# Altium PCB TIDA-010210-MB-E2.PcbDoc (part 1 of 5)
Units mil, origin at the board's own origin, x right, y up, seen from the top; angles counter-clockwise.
Board outline 11811.02 x 8661.42 mil, 4 copper layers (Top Layer, Gnd Layer, Pwr Layer, Bottom Layer), stack 94.4 mil thick; 473 components, 257 nets, 1291 pads, 289 vias.
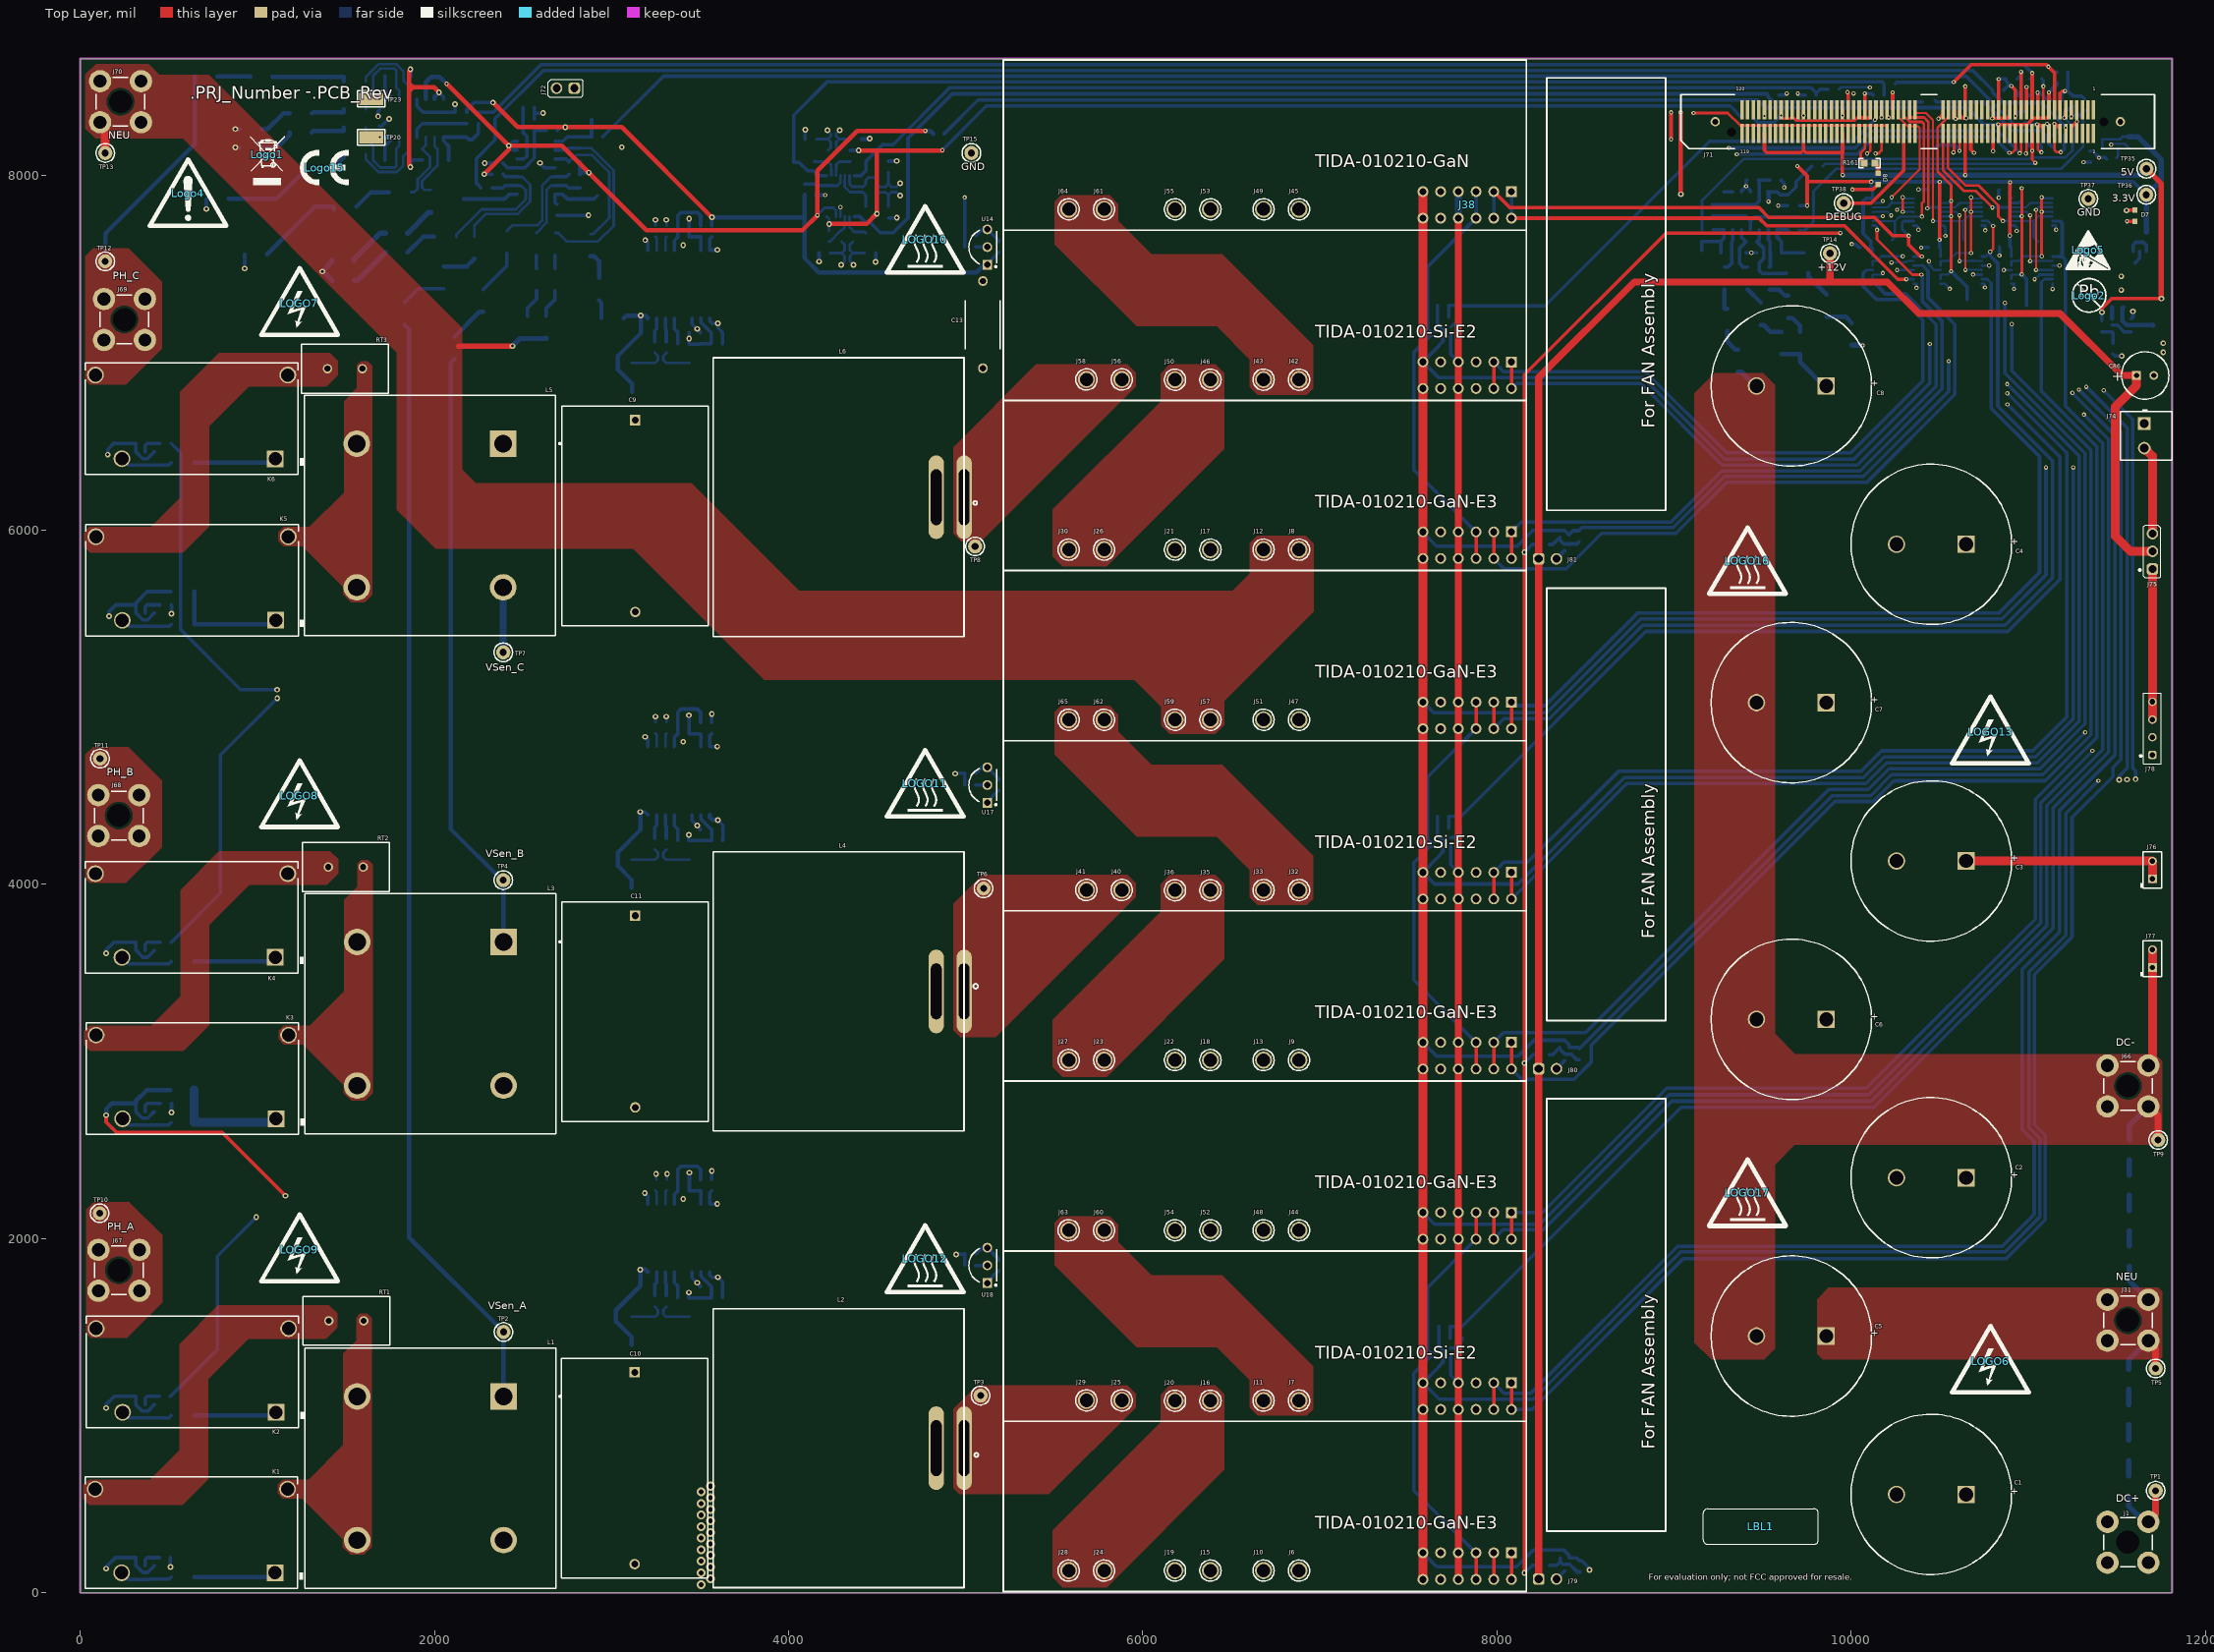
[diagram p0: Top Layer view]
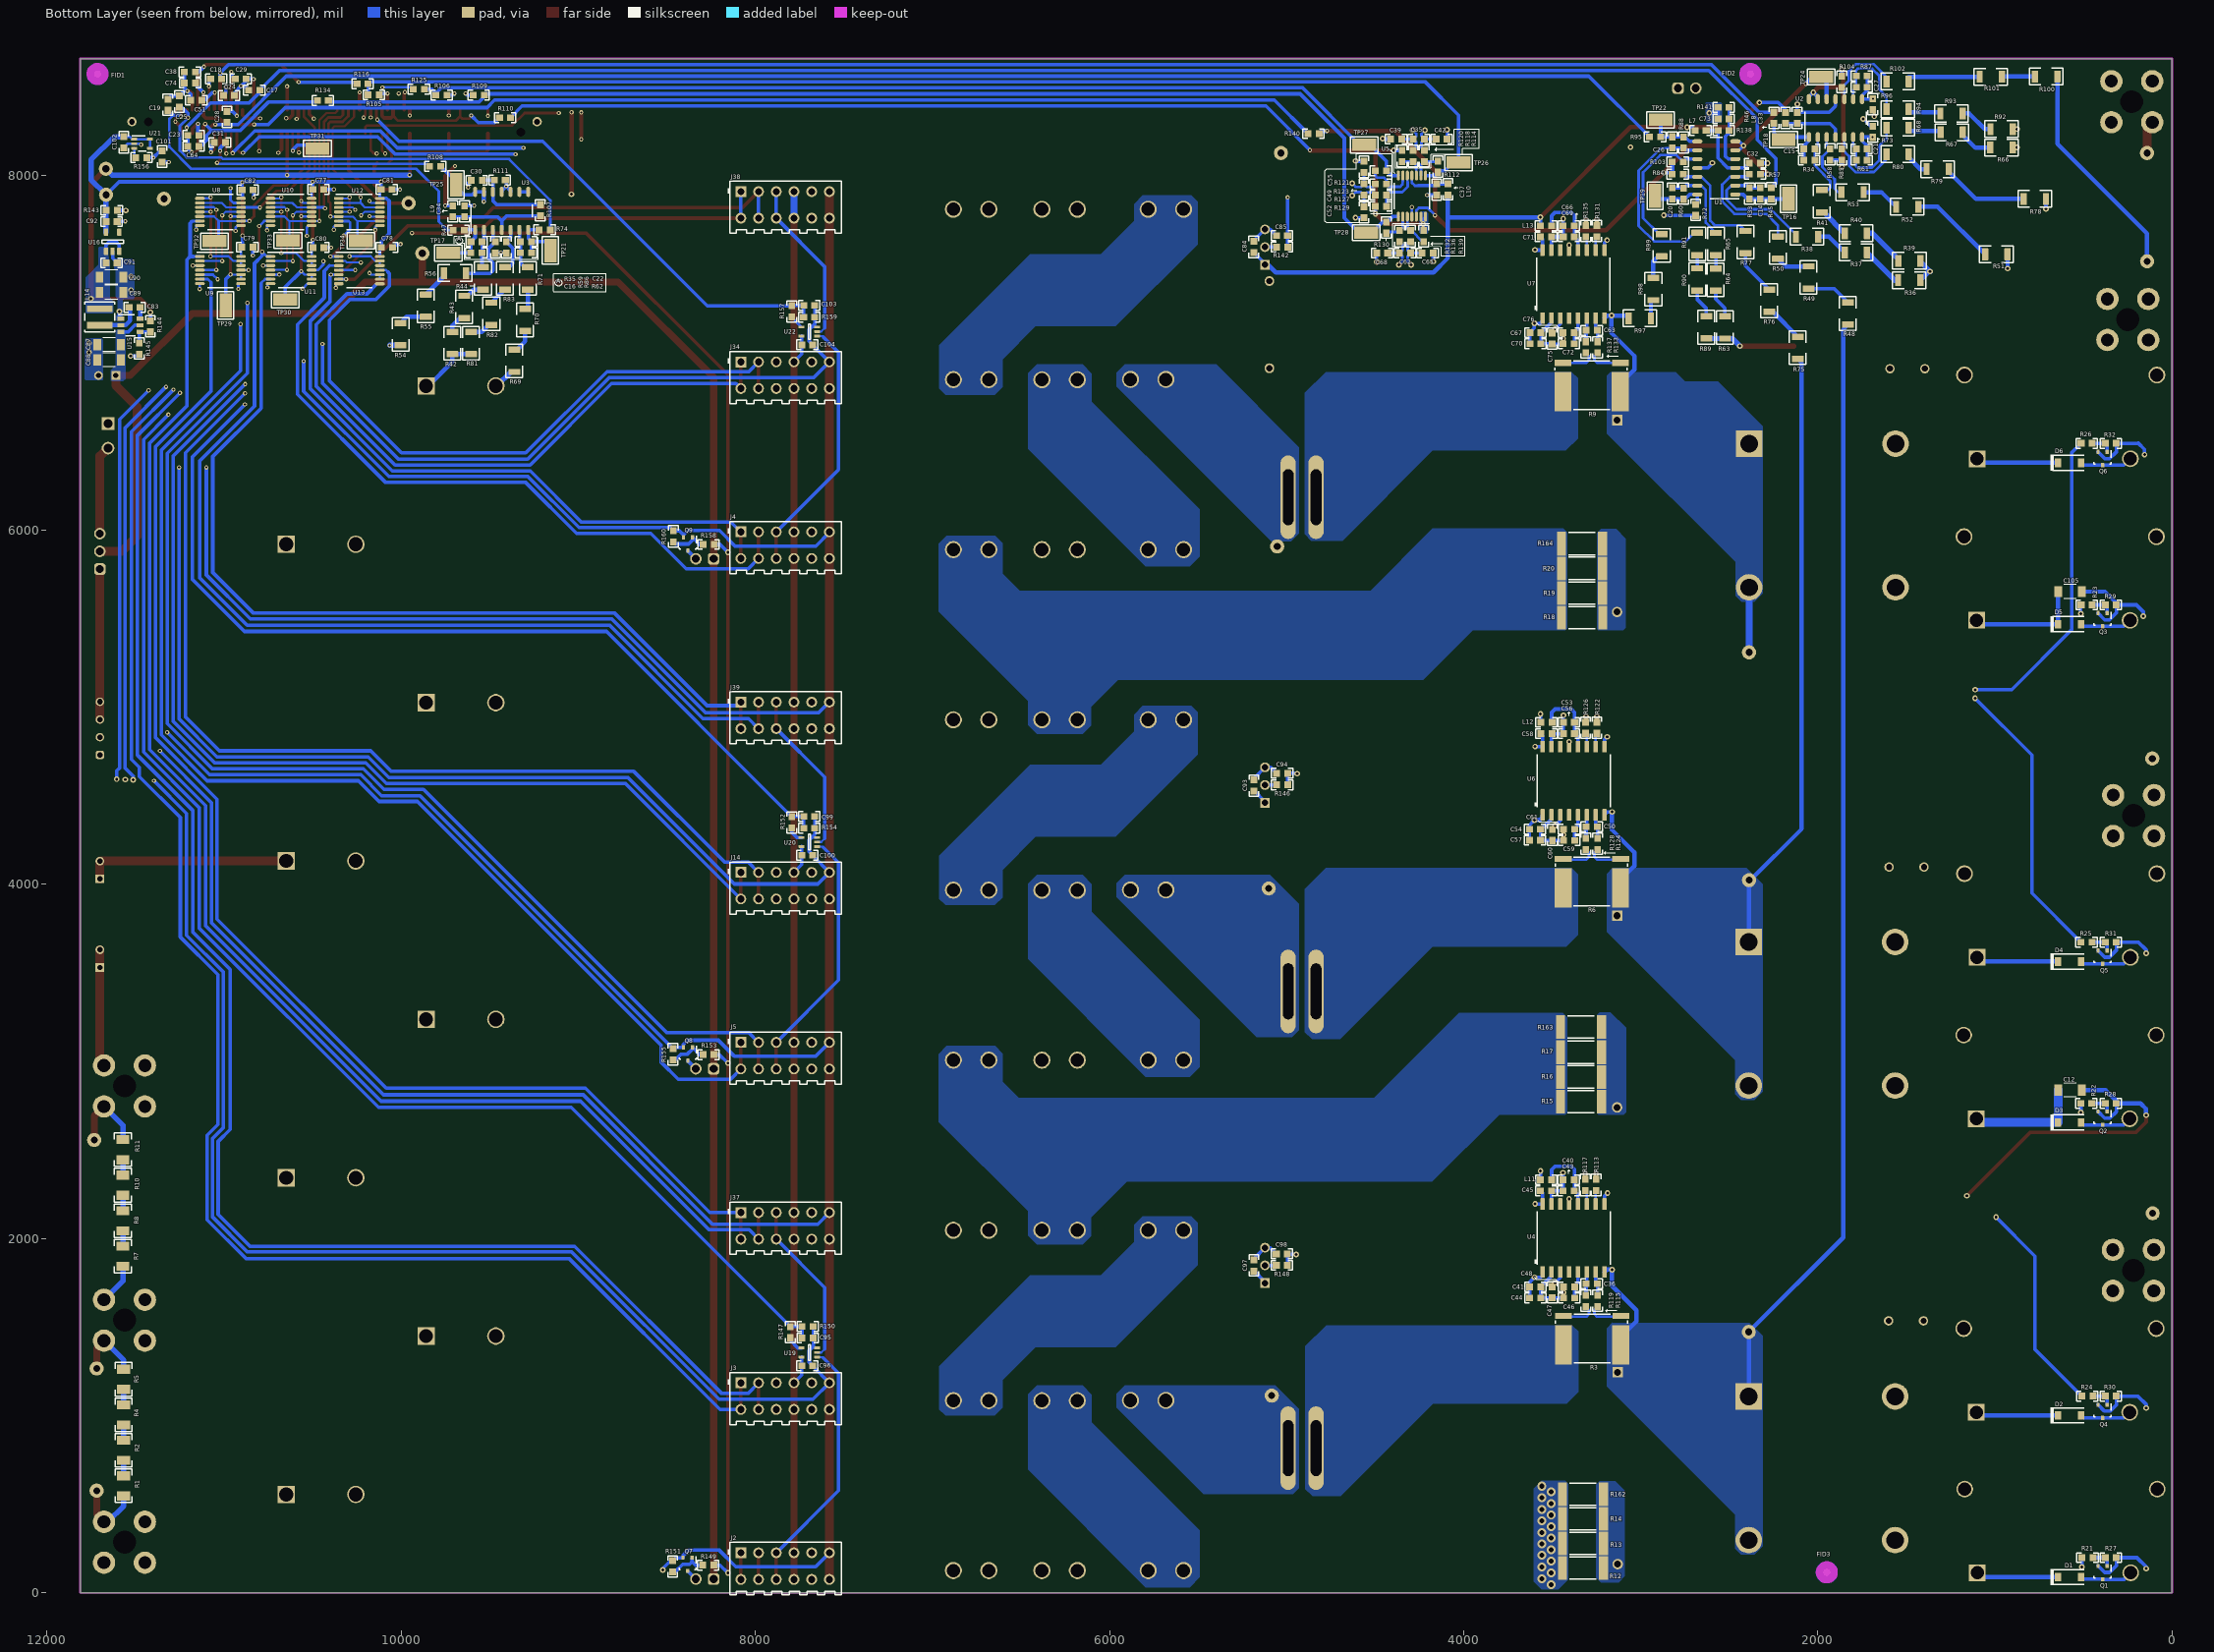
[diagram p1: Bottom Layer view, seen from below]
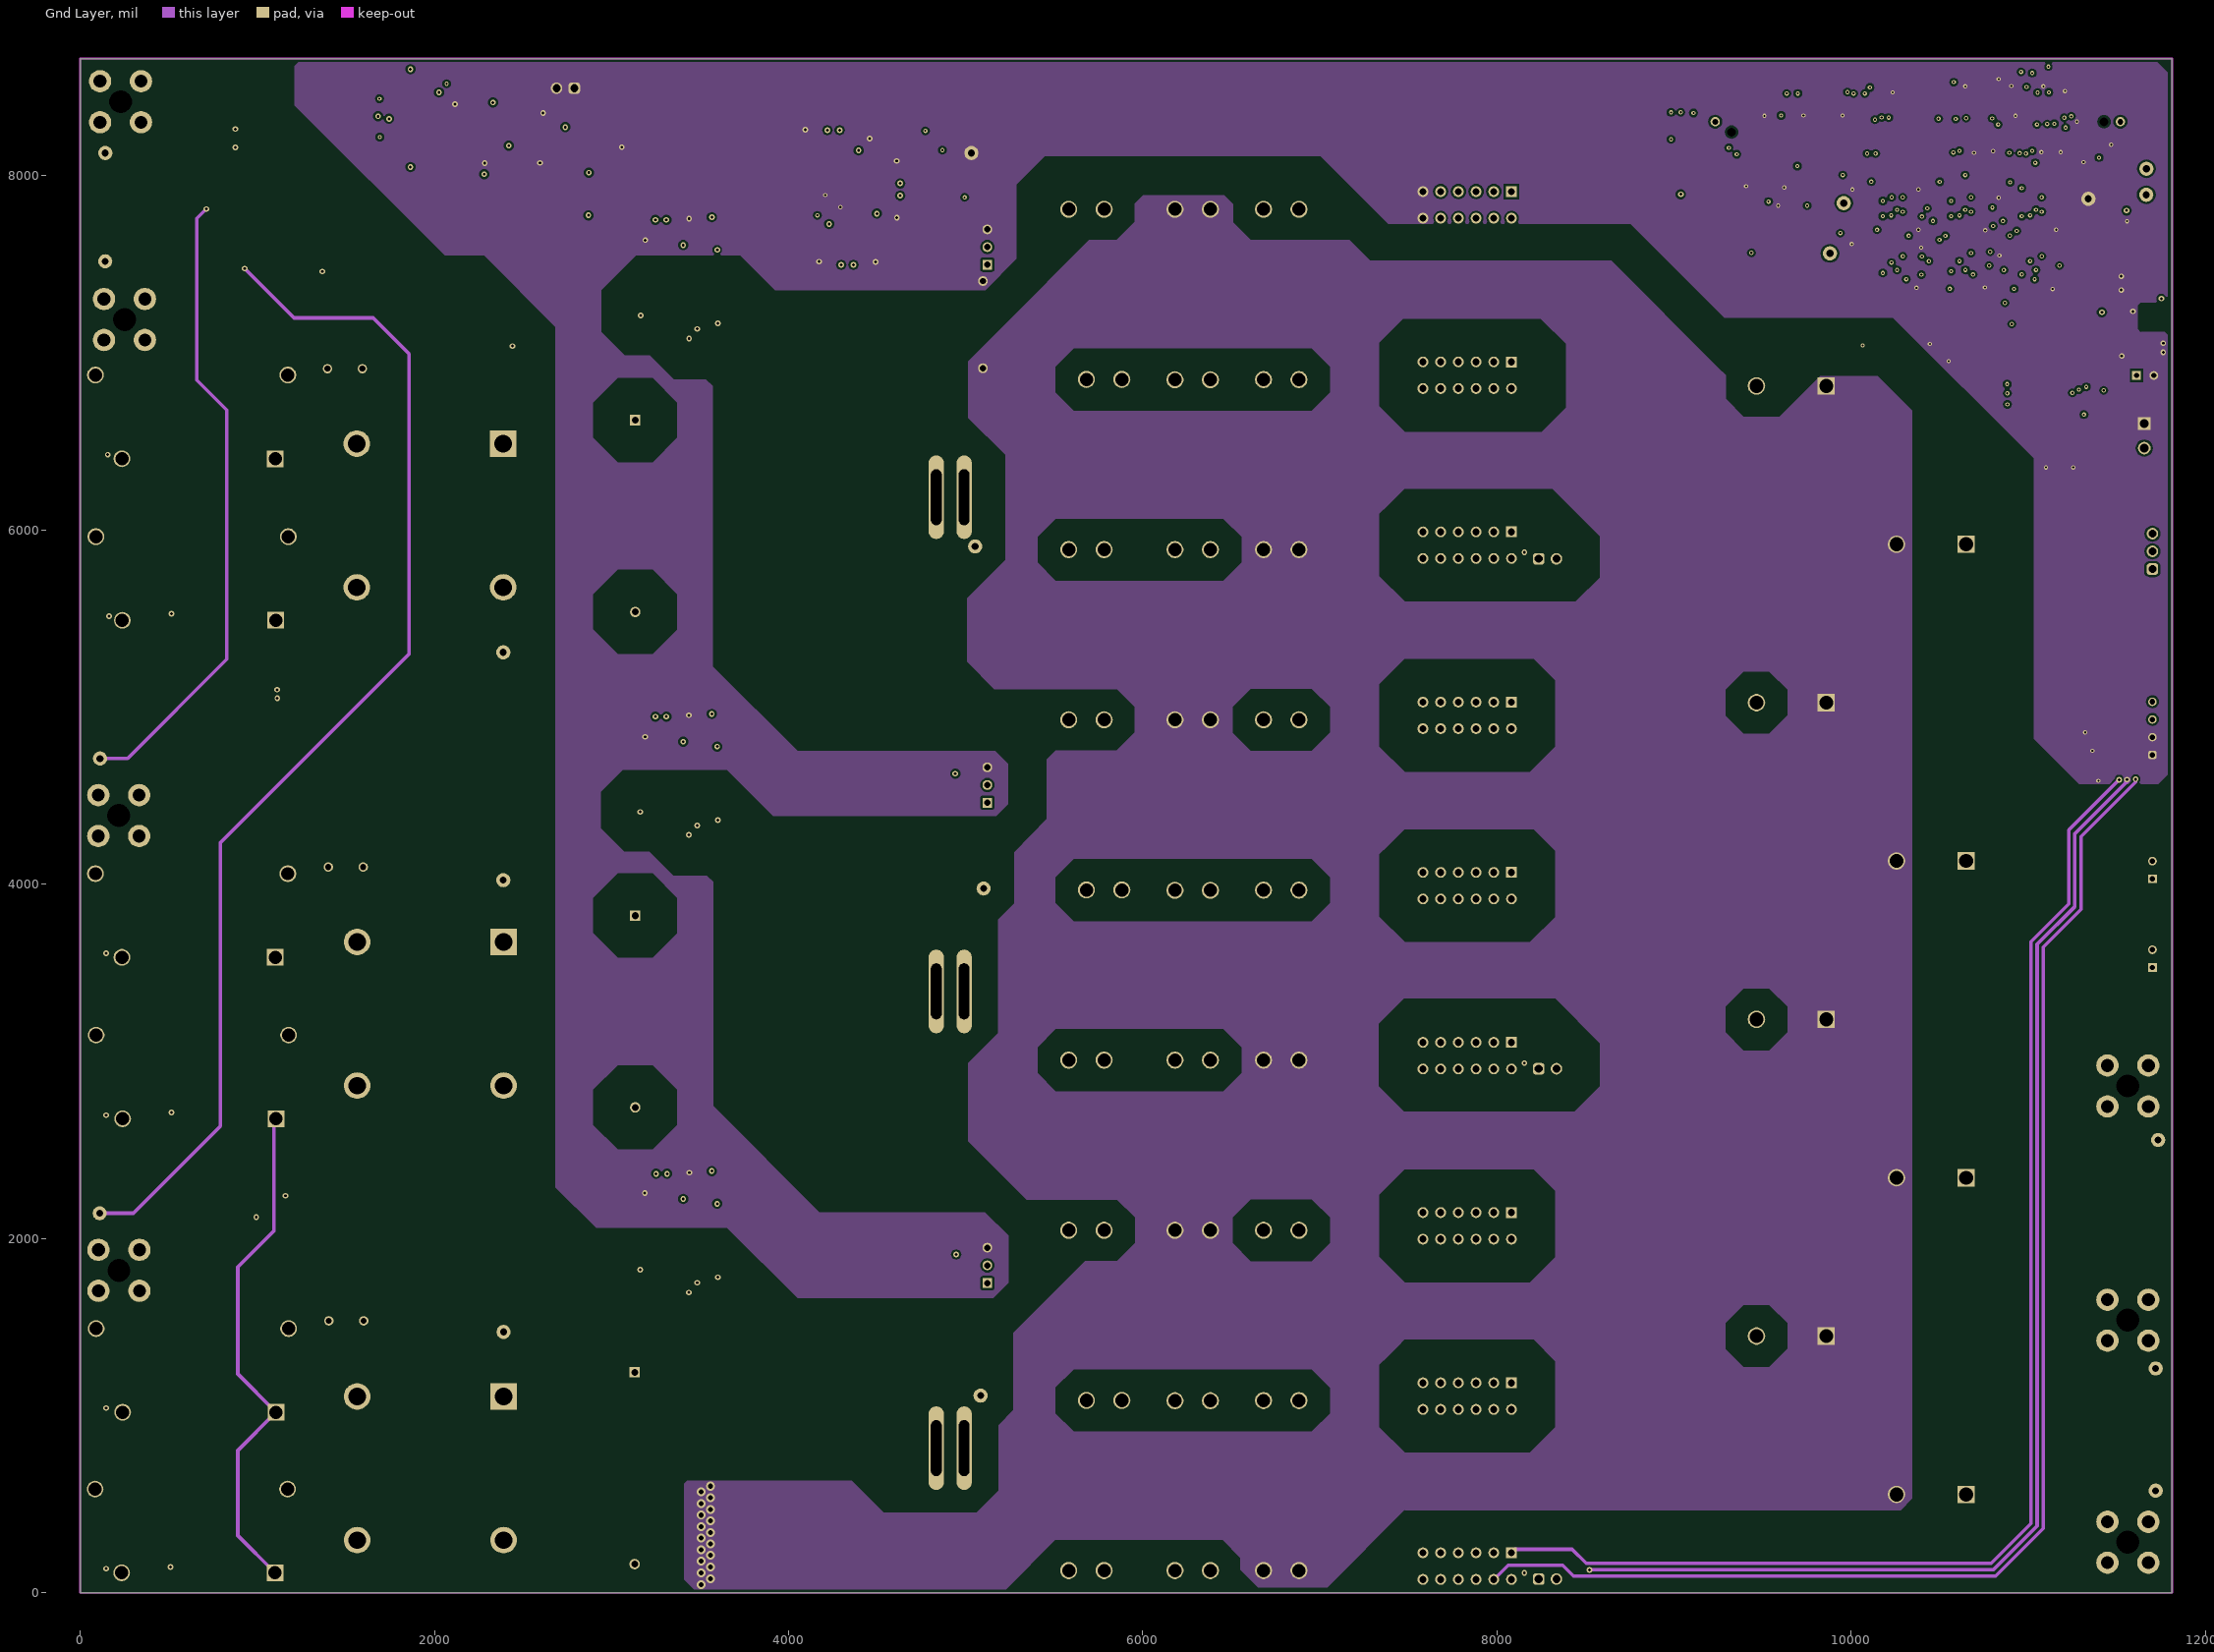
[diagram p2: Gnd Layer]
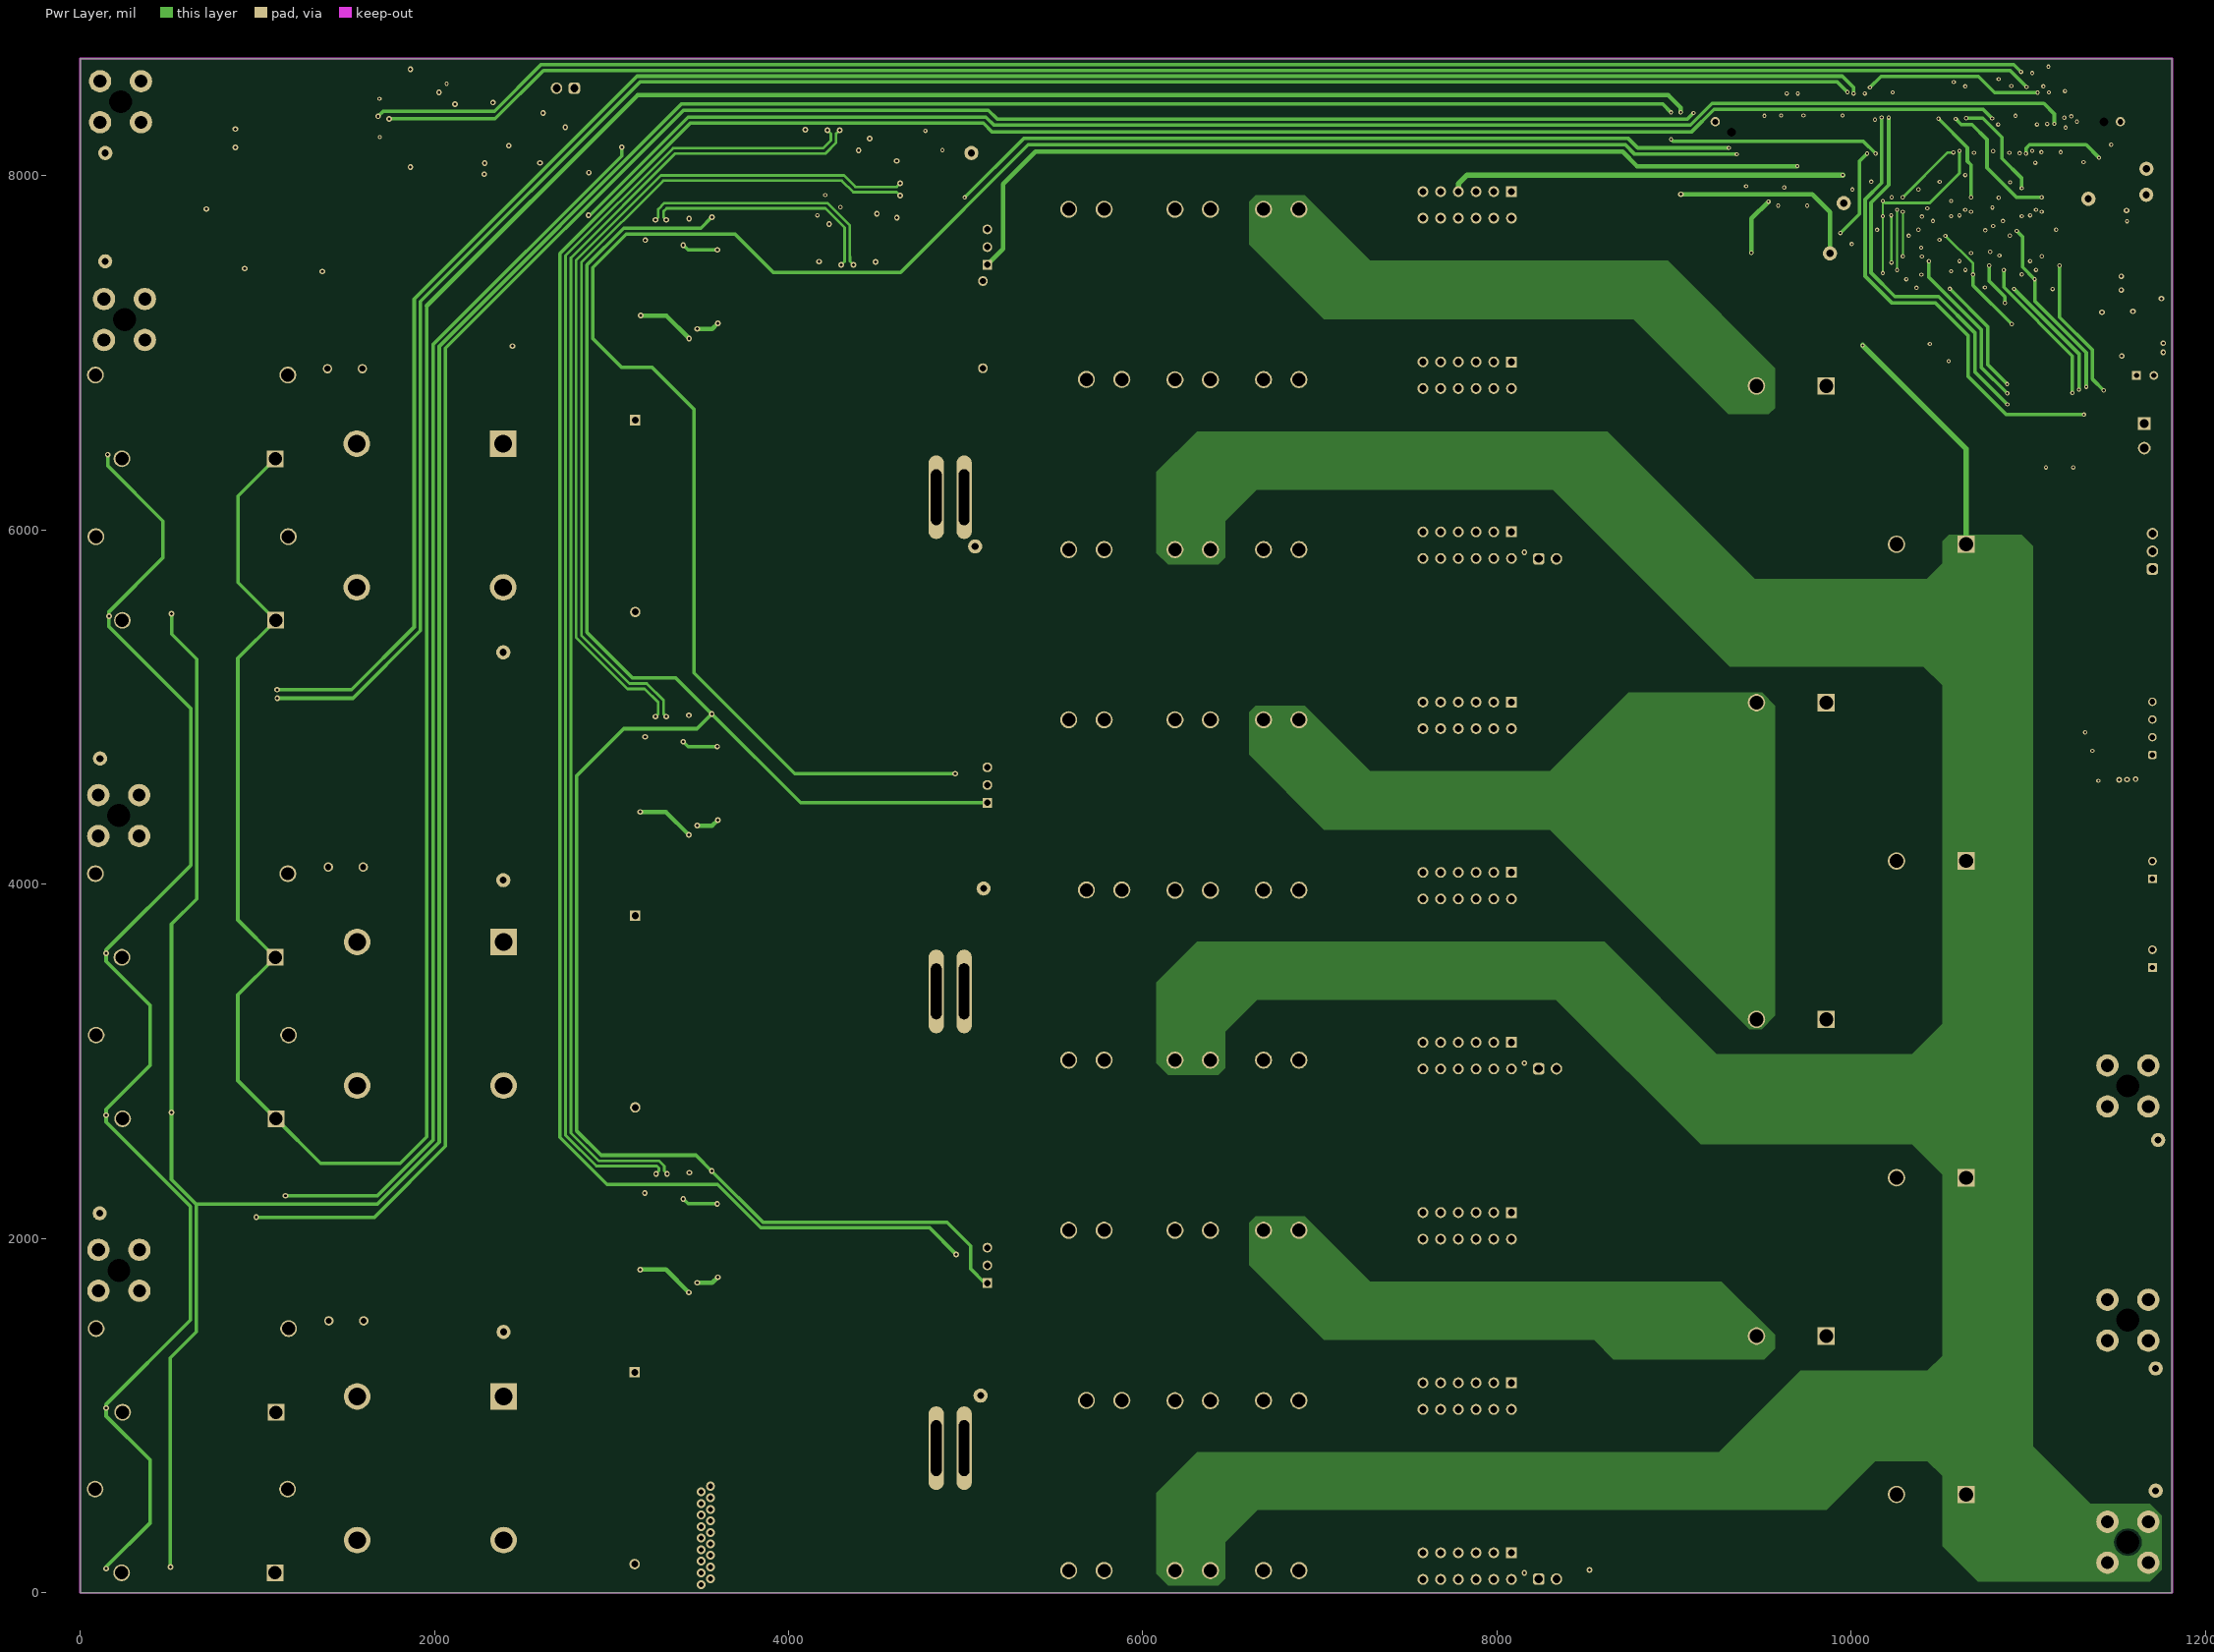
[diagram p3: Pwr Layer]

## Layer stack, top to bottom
Top Solder: solder mask 0.4, Solder Resist, Dk 3.5
Top Layer: signal copper 2.8
Dielectric 1: dielectric 12, FR-4-High Tg, Dk 4.2
Gnd Layer: signal copper 2.8
Dielectric2: core 59.2, FR-4-High Tg, Dk 4.2
Pwr Layer: signal copper 2.8
Dielectric 3: dielectric 12, FR-4-High Tg, Dk 4.2
Bottom Layer: signal copper 2.8
Bottom Solder: solder mask 0.4, Solder Resist, Dk 3.5

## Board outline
0,0 11811.02,0 11811.02,8661.42 0,8661.42

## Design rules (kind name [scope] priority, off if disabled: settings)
AcuteAngle [All] p1: minimum=4.50000000000000E+0001 checktracksonly=FALSE
AssemblyTestPointUsage [All] p1: valid=2
BoardOutlineClearance BoardOutlineClearance_MountingHoles [OnCopper and InComponentClass('Mounting Holes')] p1: gap=40 ignorepadtopadclearanceinfootprint=FALSE
BoardOutlineClearance BoardOutlineClearance_Poly [OnCopper and IsPoly] p2: gap=15 ignorepadtopadclearanceinfootprint=FALSE
BoardOutlineClearance [OnCopper and Not InComponentClass('Logo') and not InComponentClass('FiducialMark') and not InRegion(1000,500,4000,800) and not InPoly] p3: gap=0 ignorepadtopadclearanceinfootprint=FALSE
Clearance Clearance_MH [InPadClass('mh')] p1: gap=59.06 ignorepadtopadclearanceinfootprint=FALSE except(0: Arc-Hole Track-Hole SMDPad-Hole THPad-Hole Via-Hole Fill-Hole Poly-Hole Region-Hole Text-Hole)
Clearance Clearance_HV_Bottom_Layer [InLayerClass('Bottom_Layer') and InPolygon vs InNetClass('HV_Class')] p2: gap=320 ignorepadtopadclearanceinfootprint=FALSE
Clearance Clearance_HV_TOP_Layer [InLayerClass('Top_Layer') and InPolygon vs InNetClass('HV_Class')] p3: gap=320 ignorepadtopadclearanceinfootprint=FALSE
Clearance Clearance_HV_PwrLayer [InLayerClass('PWR Class') and InPolygon vs InNetClass('HV_Class')] p4: gap=200 ignorepadtopadclearanceinfootprint=FALSE
Clearance Clearance_HV_GndLayer [InLayerClass('GND_Layer') and InPolygon vs InNetClass('HV_Class')] p5: gap=200 ignorepadtopadclearanceinfootprint=FALSE
Clearance "Clearance_Poly to Poly" [InPoly vs InPoly] p6: gap=25 ignorepadtopadclearanceinfootprint=FALSE except(0: Arc-Hole Track-Hole SMDPad-Hole THPad-Hole Via-Hole Fill-Hole Poly-Hole Region-Hole Text-Hole)
Clearance Clearance_Poly [InPolygon] p7: gap=12 ignorepadtopadclearanceinfootprint=FALSE except(0: Arc-Hole Track-Hole SMDPad-Hole THPad-Hole Via-Hole Fill-Hole Poly-Hole Region-Hole Text-Hole)
Clearance [All] p8: gap=7.87 ignorepadtopadclearanceinfootprint=FALSE except(0: Arc-Arc Arc-Track Arc-SMDPad Arc-Hole Track-Hole SMDPad-Hole THPad-Hole Via-Hole Fill-Hole Poly-Hole Region-Hole Text-Hole)
ComponentClearance ComponentClearance_MountingHoles_FiducialMarks [InComponentClass('Mounting Holes') vs InComponentClass('FiducialMark')] p1: gap=30 collisioncheckmode=3 verticalgap=10 showdistances=FALSE
ComponentClearance ComponentClearance_Shunt [InComponentClass('Header') vs InComponentClass('Shunt')] p2: gap=0 collisioncheckmode=3 verticalgap=0 showdistances=FALSE
ComponentClearance ComponentClearance_Logo [InComponentClass('Logo')] p3: gap=1 collisioncheckmode=3 verticalgap=1 showdistances=FALSE
ComponentClearance ComponentClearance_ScrewToNut [(HasFootprint('NY PMS 440 0025 PH')) vs (HasFootprint('Keystone_1902C'))] p4: gap=1 collisioncheckmode=3 verticalgap=1 showdistances=FALSE
ComponentClearance ComponentClearance_MountingHoles [InComponentClass('Mounting Holes')] p5: gap=30 collisioncheckmode=3 verticalgap=100000 showdistances=FALSE
ComponentClearance ComponentClearance_SmallPassives [HasFootprint('0201*') or HasFootprint('0402*') or HasFootprint('0508') or HasFootprint('0603*') or HasFootprint('0612') or HasFootprint('0805*') or HasFootprint('0815*') or HasFootprint('0830*') or HasFootprint('1206*') or HasFootprint('1210*') or HasFootprint('1808*') or HasFootprint('1812*') or HasFootprint('1825*') or HasFootprint('2010*') or HasFootprint('2220*') or HasFootprint('2225*') or HasFootprint('2512*') or HasFootprint('2728*') or HasFootprint('3518*') vs HasFootprint('0201*') or HasFootprint('0402*') or HasFootprint('0508') or HasFootprint('0603*') or HasFootprint('0612') or HasFootprint('0805*') or HasFootprint('0815*') or HasFootprint('0830*') or HasFootprint('1206*') or HasFootprint('1210*') or HasFootprint('1808*') or HasFootprint('1812*') or HasFootprint('1825*') or HasFootprint('2010*') or HasFootprint('2220*') or HasFootprint('2225*') or HasFootprint('2512*') or HasFootprint('2728*') or HasFootprint('3518*')] p6: gap=0 collisioncheckmode=3 verticalgap=0 showdistances=FALSE
ComponentClearance ComponentClearance_THtoSMT [IsThruComponent vs IsSMTComponent] p7: gap=0 collisioncheckmode=3 verticalgap=0 showdistances=FALSE
ComponentClearance ComponentClearance_THtoTH [IsThruComponent vs IsThruComponent] p8: gap=0 collisioncheckmode=3 verticalgap=0 showdistances=FALSE
ComponentClearance [All] p9: gap=0 collisioncheckmode=3 verticalgap=0 showdistances=FALSE
DiffPairsRouting [All] p1: maxlimit=100 minlimit=10 mostfreqgap=15 toplayer_minwidth=10 toplayer_maxwidth=25 toplayer_prefwidth=15 midlayer1_minwidth=10 midlayer1_maxwidth=25 midlayer1_prefwidth=15 midlayer2_minwidth=10 midlayer2_maxwidth=25 midlayer2_prefwidth=15 bottomlayer_minwidth=10 bottomlayer_maxwidth=25 bottomlayer_prefwidth=15 maxuncoupledlength=1000
FabricationTestPointUsage TestPointUsage [All] p1: valid=2 allowmultiple=FALSE
FabricationTestpoint Testpoint [All] p1: side=3 testpointundercomponent=TRUE minsize=40 maxsize=100 preferedsize=60 minholesize=0 maxholesize=40 preferedholesize=32 testpointgrid=1 allowsidetop=TRUE allowsidebottom=TRUE usegrid=TRUE gridtolerance=0.01
FanoutControl Fanout_LCC [IsLCC] p1: bgadir=Out bgaviamode=Centered fanoutstyle=Auto fanoutdirection=Alternating viagrid=1 // Fanout_LCC (Default Rule)
FanoutControl Fanout_BGA [IsBGA] p2: bgadir=Out bgaviamode=Centered fanoutstyle=Auto fanoutdirection=Alternating viagrid=1 // Fanout_BGA (Default Rule)
FanoutControl Fanout_Default [All] p4: bgadir=Out bgaviamode=Centered fanoutstyle=Auto fanoutdirection=Alternating viagrid=1 // Fanout_Default (Default Rule)
FanoutControl Fanout_Small [(CompPinCount < 5)] p5: bgadir=Out bgaviamode=Centered fanoutstyle=Auto fanoutdirection=OutThenIn viagrid=1 // Fanout_Small (Default Rule)
Height [All] p1: minheight=0 maxheight=2500 prefheight=500
HoleSize [All] p1: absolutevalues=TRUE maxlimit=1000 minlimit=7.87 maxpercent=80.000 minpercent=20.000
MinimumAnnularRing MinimumAnnularRing_ThermalPadVias [IsVia and InAnyComponent] p1: minimumring=5.91
MinimumAnnularRing [All] p2: minimumring=5.5
MinimumSolderMaskSliver MinimumSolderMaskSliver_Logo [InComponentClass('Logo') vs InComponentClass('Logo')] p1: minsoldermaskwidth=0.7
MinimumSolderMaskSliver [All] p2: minsoldermaskwidth=3.94
PlaneConnect [All] p1: planeconnectstyle=Direct reliefexpansion=10 reliefentries=4 reliefconductorwidth=10 reliefairgap=10
PolygonConnect [All] p1: connectstyle=Direct reliefconductorwidth=10 reliefentries=4 polygonreliefangle="90 Angle" airgapwidth=10
RoutingVias ThermalPadVias [IsVia and InAnyComponent] p1: holewidth=7.87 width=19.68 viastyle="Through Hole" minholewidth=7.87 minwidth=19.68 maxholewidth=12.99 maxwidth=23.62
RoutingVias [All] p2: holewidth=16 width=32 viastyle="Through Hole" minholewidth=12 minwidth=24 maxholewidth=28 maxwidth=52
SilkToBoardRegionClearance [Not ((IsComment or IsDesignator) And (Hide <> 'False')) and not InRegion(1000,500,4000,800)] p1:
SilkToSilkClearance SilkToSilkClearance_Pb-FreeLogo [(HasFootprint('Pb-Free_Overlay_Medium') OR HasFootprint('Pb-Free_Overlay_Small')) vs (HasFootprint('Pb-Free_Overlay_Medium') OR HasFootprint('Pb-Free_Overlay_Small'))] p1: silktosilkclearance=0
SilkToSilkClearance [All] p2: silktosilkclearance=4
SilkToSolderMaskClearance SilkToComponentPadClearance [(IsPad or IsFill or IsRegion) and InAnycomponent] p1: minsilkscreentomaskgap=5 clearancetoexposedcopper=TRUE
SilkToSolderMaskClearance "Silk to Solder Mask Opening" [All] p2: minsilkscreentomaskgap=4 clearancetoexposedcopper=FALSE
SolderMaskExpansion [All] p1: expansion=1.97 istentingtop=FALSE
Width [All] p1: maxlimit=100 minlimit=9 preferedwidth=20 checkconnectedcopper=TRUE
14 further rules are at their usual default settings.

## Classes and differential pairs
component class "Power Supply and Protection-Pg3": C83 C84 C85 C86 C87 C88 C89 C90 C91 C92 C93 C94 C95 C96 C97 C98 C99 C100 C101 C102 C103 C104 D7 J72 J74 J75 J76 J77 J78 J79 J80 J81 L14 Q7 Q8 Q9 R142 R143 R144 R145 R146 R147 R148 R149 R150 R151 R152 R153 R154 R155 R156 R157 R158 R159 R160 TP35 TP36 TP37 U14 U15 U16 U17 U18 U19 U20 U21 U22
component class "Voltage Sensing-Pg4": C14 C15 C16 C17 C18 C19 C20 C21 C22 C23 C24 C25 C26 C27 C28 C29 C30 C31 C32 C33 C34 C73 C74 L7 L8 L9 R33 R34 R35 R36 R37 R38 R39 R40 R41 R42 R43 R44 R45 R46 R47 R48 R49 R50 R51 R52 R53 R54 R55 R56 R57 R58 R59 R60 R61 R62 R63 R64 R65 R66 R67 R68 R69 R70 R71 R72 R73 R74 R75 R76 R77 R78 R79 R80 R81 R82 R83 R84 R85 R86 R87 R88 R89 R90 R91 R92 R93 R94 R95 R96 R97 R98 R99 R100 R101 R102 R103 R104 R107 R108 R111 R138 R140 R141 TP16 TP17 TP18 TP19 TP20 TP21 TP22 TP23 TP24 TP25 U1 U2 U3
component class Hardware-Pg7: FID1 FID2 FID3 LBL1 Logo1 Logo2 Logo3 Logo4 Logo5 LOGO6 LOGO7 LOGO8 LOGO9 LOGO10 LOGO11 LOGO12 LOGO13 Logo15 LOGO16 LOGO17 ZZ1 ZZ2 ZZ3 ZZ4
component class FiducialMark: FID1 FID2 FID3
component class AssemblyNote: ZZ1 ZZ2 ZZ3 ZZ4
component class Label: LBL1
component class "Current Sensing-Pg5": C35 C36 C37 C38 C39 C40 C41 C42 C43 C44 C45 C46 C47 C48 C49 C50 C51 C52 C53 C54 C55 C56 C57 C58 C59 C60 C61 C62 C63 C64 C65 C66 C67 C68 C69 C70 C71 C72 C75 C76 L10 L11 L12 L13 R105 R106 R109 R110 R112 R113 R114 R115 R116 R117 R118 R119 R120 R121 R122 R123 R124 R125 R126 R127 R128 R129 R130 R131 R132 R133 R134 R135 R136 R137 R139 TP26 TP27 TP28 U4 U5 U6 U7
component class "Power Stage-Pg2": C1 C2 C3 C4 C5 C6 C7 C8 C9 C10 C11 C12 C13 C105 D1 D2 D3 D4 D5 D6 J1 J2 J3 J4 J5 J6 J7 J8 J9 J10 J11 J12 J13 J14 J15 J16 J17 J18 J19 J20 J21 J22 J23 J24 J25 J26 J27 J28 J29 J30 J31 J32 J33 J34 J35 J36 J37 J38 J39 J40 J41 J42 J43 J44 J45 J46 J47 J48 J49 J50 J51 J52 J53 J54 J55 J56 J57 J58 J59 J60 J61 J62 J63 J64 J65 J66 J67 J68 J69 J70 K1 K2 K3 K4 K5 K6 L1 L2 L3 L4 L5 L6 Q1 Q2 Q3 Q4 Q5 Q6 R1 R2 R3 R4 R5 R6 R7 R8 R9 R10 R11 R12 R13 R14 R15 R16 R17 R18 R19 R20 R21 R22 R23 R24 R25 R26 R27 R28 R29 R30 R31 R32 R162 R163 R164 RT1 RT2 RT3 TP1 TP2 TP3 TP4 TP5 TP6 TP7 TP8 TP9 TP10 TP11 TP12 TP13 TP14 TP15
component class "Controller Card-Pg6": C77 C78 C79 C80 C81 C82 D8 J71 R161 TP29 TP30 TP31 TP32 TP33 TP34 TP38 U8 U9 U10 U11 U12 U13
component class Header: J72 J75 J79 J80 J81
pad class mh: H1-1 H2-1 H3-1 H4-1 H9-1 H10-1 H11-1 H12-1 H13-1

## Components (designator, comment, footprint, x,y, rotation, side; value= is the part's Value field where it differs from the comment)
C1 "ESG157M500AQ5" ESG157M500AQ5 10451.66,555 r180 top locked value=150uF
C2 "ESG157M500AQ5" ESG157M500AQ5 10451.66,2343 r180 top locked value=150uF
C3 "ESG157M500AQ5" ESG157M500AQ5 10451.66,4131 r180 top locked value=150uF
C4 "ESG157M500AQ5" ESG157M500AQ5 10451.66,5919 r180 top locked value=150uF
C5 "ESG157M500AQ5" ESG157M500AQ5 9661.11,1449 r180 top locked value=150uF
C6 "ESG157M500AQ5" ESG157M500AQ5 9661.11,3237 r180 top locked value=150uF
C7 "ESG157M500AQ5" ESG157M500AQ5 9661.11,5025 r180 top locked value=150uF
C8 "ESG157M500AQ5" ESG157M500AQ5 9661.11,6813 r180 top locked value=150uF
C9 "B32924D3475K" B32924_31mm 3134,6078.34 r270 top locked value=4.7uF
C10 "B32924D3475K" B32924_31mm 3131,703 r270 top locked value=4.7uF
C11 "B32924D3475K" B32924_31mm 3134,3281.22 r270 top locked value=4.7uF
C12 "CGA5L1X7R1V106K160AC" 1206_190 577,2838 r180 bottom value=10uF
C13 "VY1222K47Y5UQ6TVX" VY1_1200x500_V 5097,7159 r270 top value=2200pF
C14 "06035A471JAT2A" 0603 2325.29,7899.53 r90 bottom value=470pF
C15 "06035A471JAT2A" 0603 2048.98,8150.89 r180 bottom value=470pF
C16 "06035A471JAT2A" 0603 9574.12,7564.63 r180 bottom value=470pF
C17 "C0603X103K5RACTU" 0603 10828.5,8482.84 r0 bottom value=0.01uF
C18 "C0603X103K5RACTU" 0603 11043.61,8546 r0 bottom value=0.01uF
C19 "C0603X103K5RACTU" 0603 11315.73,8400.5 r90 bottom value=0.01uF
C20 "06035A471JAT2A" 0603 2822.38,7899.53 r90 bottom value=470pF
C21 "06035A471JAT2A" 0603 1752.98,8150.96 r0 bottom value=470pF
C22 "06035A471JAT2A" 0603 9294.14,7627.47 r0 bottom value=470pF
C23 "C0603X103K5RACTU" 0603 11171.62,8228 r0 bottom value=0.01uF
C24 "C0603X103K5RACTU" 0603 10971.17,8453 r180 bottom value=0.01uF
C25 "C0603X103K5RACTU" 0603 11250.84,8419 r90 bottom value=0.01uF
C26 "06035A471JAT2A" 0603 2822.38,8187.53 r270 bottom value=470pF
C27 "06035A471JAT2A" 0603 1752.98,8498.98 r0 bottom value=470pF
C28 "C0603X103K5RACTU" 0603 10982,8331.39 r90 bottom value=0.01uF
C29 "C0603X103K5RACTU" 0603 10905,8546 r180 bottom value=0.01uF
C30 "C0603X104K3RACTU" 0603 9572,7974 r180 bottom value=0.1uF
C31 "C0603X103K5RACTU" 0603 11022.5,8187 r0 bottom value=0.01uF
C32 "C0603X104K3RACTU" 0603 2355.83,8070.53 r0 bottom value=0.1uF
C33 "C0603X104K3RACTU" 0603 2116.98,8325.97 r270 bottom value=0.1uF
C34 "C0603X104K3RACTU" 0603 9641,7799 r270 bottom value=0.1uF
C35 "GRM1885C1H332JA01D" 0603 4253.47,8206.91 r0 bottom value=3300pF
C36 "C0603X103K5RACTU" 0603 3277,1744 r0 bottom value=0.01uF
C37 "C0603X104K3RACTU" 0603 4153,7922 r90 bottom value=0.1uF
C38 "GRM1885C1H221JA01D" 0603 11191.55,8585 r0 bottom value=220pF
C39 "06035A331JAT2A" 0603 4381.47,8206.91 r0 bottom value=330pF
C40 "GRJ188R71E105KE11D" 0603 3407.94,2331.78 r0 bottom value=1uF
C41 "C0603X104K3RACTU" 0603 3595.94,1726.46 r0 bottom value=0.1uF
C42 "06035A331JAT2A" 0603 4125.02,8206.91 r180 bottom value=330pF
C43 "GRM188R71H102JA01D" 0603 3407.94,2268.78 r0 bottom value=1000pF
C44 "GRJ188R71E105KE11D" 0603 3595.94,1663.46 r180 bottom value=1uF
C45 "C0603X104K3RACTU" 0603 3534.94,2268.78 r0 bottom value=0.1uF
C46 "C0603X104K3RACTU" 0603 3404.94,1663.46 r180 bottom value=0.1uF
C47 "GRM188R71H102JA01D" 0603 3500,1696.5 r270 bottom value=1000pF
C48 "GRM188R71H102JA01D" 0603 3404.94,1726.46 r0 bottom value=1000pF
C49 "GRM1885C1H332JA01D" 0603 4563.47,7921.76 r270 bottom value=3300pF
C50 "C0603X103K5RACTU" 0603 3277.43,4324 r0 bottom value=0.01uF
C51 "GRM1885C1H221JA01D" 0603 11155.48,8426 r0 bottom value=220pF
C52 "06035A331JAT2A" 0603 4563.47,7793.76 r270 bottom value=330pF
C53 "GRJ188R71E105KE11D" 0603 3405.86,4913.74 r0 bottom value=1uF
C54 "C0603X104K3RACTU" 0603 3597.55,4311 r0 bottom value=0.1uF
C55 "06035A331JAT2A" 0603 4563.47,8050.22 r90 bottom value=330pF
C56 "GRM188R71H102JA01D" 0603 3405.86,4849.74 r0 bottom value=1000pF
C57 "GRJ188R71E105KE11D" 0603 3597.55,4248 r180 bottom value=1uF
C58 "C0603X104K3RACTU" 0603 3532.86,4849.74 r0 bottom value=0.1uF
C59 "C0603X104K3RACTU" 0603 3404.93,4247 r180 bottom value=0.1uF
C60 "GRM188R71H102JA01D" 0603 3499,4278 r270 bottom value=1000pF
C61 "GRM188R71H102JA01D" 0603 3404.93,4310 r0 bottom value=1000pF
C62 "GRM1885C1H332JA01D" 0603 4331.53,7562.91 r180 bottom value=3300pF
C63 "C0603X103K5RACTU" 0603 3277.54,7127 r0 bottom value=0.01uF
C64 "GRM1885C1H221JA01D" 0603 11171.87,8165.16 r0 bottom value=220pF
C65 "06035A331JAT2A" 0603 4203.53,7562.91 r180 bottom value=330pF
C66 "GRJ188R71E105KE11D" 0603 3407,7716.78 r0 bottom value=1uF
C67 "C0603X104K3RACTU" 0603 3595,7114 r0 bottom value=0.1uF
C68 "06035A331JAT2A" 0603 4459.98,7562.91 r0 bottom value=330pF
C69 "GRM188R71H102JA01D" 0603 3406.93,7654.61 r0 bottom value=1000pF
C70 "GRJ188R71E105KE11D" 0603 3595,7051 r180 bottom value=1uF
C71 "C0603X104K3RACTU" 0603 3535,7654.61 r0 bottom value=0.1uF
C72 "C0603X104K3RACTU" 0603 3407,7051 r180 bottom value=0.1uF
C73 "C0603X104K3RACTU" 0603 2533,8320.39 r180 bottom value=0.1uF
C74 "C0603X103K5RACTU" 0603 11191.17,8523 r0 bottom value=0.01uF
C75 "GRM188R71H102JA01D" 0603 3500.93,7081 r270 bottom value=1000pF
C76 "GRM188R71H102JA01D" 0603 3407,7114 r0 bottom value=1000pF
C77 "C0603X104K3RACTU" 0603 10466.82,7922.18 r0 bottom value=0.1uF
C78 "C0603X104K3RACTU" 0603 10079.19,7594.78 r0 bottom value=0.1uF
C79 "C0603X104K3RACTU" 0603 10867.35,7596.18 r0 bottom value=0.1uF
C80 "C0603X104K3RACTU" 0603 10465.82,7594.18 r0 bottom value=0.1uF
C81 "C0603X104K3RACTU" 0603 10081.19,7921.78 r0 bottom value=0.1uF
C82 "C0603X104K3RACTU" 0603 10866,7920 r0 bottom value=0.1uF
C83 "C0603X104K3RACTU" 0603 11504,7256.91 r180 bottom value=0.1uF
C84 "C0603X104K3RACTU" 0603 5185.05,7598.06 r270 bottom value=0.1uF
C85 "C0603X104K3RACTU" 0603 5026.05,7661.11 r180 bottom value=0.1uF
C86 "EEU-EB1E101S" CAPPR250W50D630H1120 11659,6871.91 r0 top value=100uF
C87 "CGA5L1X7R1V106K160AC" 1206_190 11648,7044.93 r0 bottom value=10uF
C88 "CGA5L1X7R1V106K160AC" 1206_190 11648,6958.93 r0 bottom value=10uF
C89 "GRM31CR71A226KE15L" 1206_180 11635,7340.91 r180 bottom value=22uF
C90 "GRM31CR71A226KE15L" 1206_180 11635,7426.91 r180 bottom value=22uF
C91 "CC0603KRX7R7BB225" 0603 11634.01,7507.71 r180 bottom value=2.2uF
C92 "CC0603KRX7R7BB225" 0603 11634.01,7740.71 r180 bottom value=2.2uF
C93 "C0603X104K3RACTU" 0603 5185,4557 r270 bottom value=0.1uF
C94 "C0603X104K3RACTU" 0603 5025,4626 r180 bottom value=0.1uF
C95 "06035A331JAT2A" 0603 7704,1438.26 r180 bottom value=330pF
C96 "C0603X104K3RACTU" 0603 7706.09,1281.34 r0 bottom value=0.1uF
C97 "C0603X104K3RACTU" 0603 5185,1847.81 r270 bottom value=0.1uF
C98 "C0603X104K3RACTU" 0603 5027,1913 r180 bottom value=0.1uF
C99 "06035A331JAT2A" 0603 7695,4382 r180 bottom value=330pF
C100 "C0603X104K3RACTU" 0603 7706,4163.13 r0 bottom value=0.1uF
C101 "C0603X104K3RACTU" 0603 11348.68,8108 r90 bottom value=0.1uF
C102 "C0603X104K3RACTU" 0603 11564.73,8188.75 r90 bottom value=0.1uF
C103 "06035A331JAT2A" 0603 7695,7267 r180 bottom value=330pF
C104 "C0603X104K3RACTU" 0603 7706,7045.02 r0 bottom value=0.1uF
C105 "CGA5L1X7R1V106K160AC" 1206_190 577,5652 r180 bottom value=10uF
D1 "1N4148WQ-7-F" SOD-123 579,88 r180 bottom value=100V
D2 "1N4148WQ-7-F" SOD-123 579,1001 r180 bottom value=100V
D3 "1N4148WQ-7-F" SOD-123 579,2655 r180 bottom value=100V
D4 "1N4148WQ-7-F" SOD-123 579,3563 r180 bottom value=100V
D5 "1N4148WQ-7-F" SOD-123 579,5468 r180 bottom value=100V
D6 "1N4148WQ-7-F" SOD-123 579,6379 r180 bottom value=100V
D7 "150060VS55040" WL-SMCD-0603 11601,7773.91 r90 top value=Green
D8 "150060VS55040" WL-SMCD-0603 10150.54,7982 r90 top value=Green
FID1 "Fiducial" Fiducial10-30 11713,8574 r180 bottom
FID2 "Fiducial" Fiducial10-30 2381,8574 r180 bottom
FID3 "Fiducial" Fiducial10-30 1950,115 r180 bottom
J1 "74650073R" Wurth_WP-THRBU 11561.45,285 r0 top locked
J2 "0448120024" Molex_0448120024#1 7831.32,150.11 r180 bottom
J3 "0448120024" Molex_0448120024#1 7831.32,1109.74 r180 bottom
J4 "0448120024" Molex_0448120024#1 7831.32,5913.89 r180 bottom
J5 "0448120024" Molex_0448120024#1 7831.32,3032 r180 bottom
J6 "Suggest using a net name here" Mill-Max_0312-0-15-15-34-27-10-0 6881.32,125.11 r0 top
J7 "Suggest using a net name here" Mill-Max_0312-0-15-15-34-27-10-0 6881.32,1084.74 r0 top
J8 "Suggest using a net name here" Mill-Max_0312-0-15-15-34-27-10-0 6881.32,5888.89 r0 top
J9 "Suggest using a net name here" Mill-Max_0312-0-15-15-34-27-10-0 6881.32,3007 r0 top
J10 "Suggest using a net name here" Mill-Max_0312-0-15-15-34-27-10-0 6681.32,125.11 r0 top
J11 "Suggest using a net name here" Mill-Max_0312-0-15-15-34-27-10-0 6681.32,1084.74 r0 top
J12 "Suggest using a net name here" Mill-Max_0312-0-15-15-34-27-10-0 6681.32,5888.89 r0 top
J13 "Suggest using a net name here" Mill-Max_0312-0-15-15-34-27-10-0 6681.32,3007 r0 top
J14 "0448120024" Molex_0448120024#1 7831.32,3991.63 r180 bottom
J15 "Suggest using a net name here" Mill-Max_0312-0-15-15-34-27-10-0 6381.32,125.11 r0 top
J16 "Suggest using a net name here" Mill-Max_0312-0-15-15-34-27-10-0 6381.32,1083.95 r0 top
J17 "Suggest using a net name here" Mill-Max_0312-0-15-15-34-27-10-0 6381.32,5888.89 r0 top
J18 "Suggest using a net name here" Mill-Max_0312-0-15-15-34-27-10-0 6381.32,3007 r0 top
J19 "Suggest using a net name here" Mill-Max_0312-0-15-15-34-27-10-0 6181.32,125.11 r0 top
J20 "Suggest using a net name here" Mill-Max_0312-0-15-15-34-27-10-0 6181.32,1083.95 r0 top
J21 "Suggest using a net name here" Mill-Max_0312-0-15-15-34-27-10-0 6181.32,5888.89 r0 top
J22 "Suggest using a net name here" Mill-Max_0312-0-15-15-34-27-10-0 6181.32,3007 r0 top
J23 "Suggest using a net name here" Mill-Max_0312-0-15-15-34-27-10-0 5781.32,3007 r0 top
J24 "Suggest using a net name here" Mill-Max_0312-0-15-15-34-27-10-0 5781.32,125.11 r0 top
J25 "Suggest using a net name here" Mill-Max_0312-0-15-15-34-27-10-0 5881.32,1085.74 r0 top
J26 "Suggest using a net name here" Mill-Max_0312-0-15-15-34-27-10-0 5781.32,5888.89 r0 top
J27 "Suggest using a net name here" Mill-Max_0312-0-15-15-34-27-10-0 5581.32,3007 r0 top
J28 "Suggest using a net name here" Mill-Max_0312-0-15-15-34-27-10-0 5581.32,125.11 r0 top
J29 "Suggest using a net name here" Mill-Max_0312-0-15-15-34-27-10-0 5681.32,1085.74 r0 top
J30 "Suggest using a net name here" Mill-Max_0312-0-15-15-34-27-10-0 5581.32,5888.89 r0 top
J31 "74650073R" Wurth_WP-THRBU 11561.45,1538.5 r0 top locked
J32 "Suggest using a net name here" Mill-Max_0312-0-15-15-34-27-10-0 6881.32,3966.63 r0 top
J33 "Suggest using a net name here" Mill-Max_0312-0-15-15-34-27-10-0 6681.32,3966.63 r0 top
J34 "0448120024" Molex_0448120024#1 7831.32,6873.52 r180 bottom
J35 "Suggest using a net name here" Mill-Max_0312-0-15-15-34-27-10-0 6381.32,3965.84 r0 top
J36 "Suggest using a net name here" Mill-Max_0312-0-15-15-34-27-10-0 6181.32,3965.84 r0 top
J37 "0448120024" Molex_0448120024#1 7831.32,2071.37 r180 bottom
J38 "0448120024" Molex_0448120024#2 7831.32,7835.15 r180 top
J39 "0448120024" Molex_0448120024#1 7831.32,4953.26 r180 bottom
J40 "Suggest using a net name here" Mill-Max_0312-0-15-15-34-27-10-0 5881.32,3967.63 r0 top
J41 "Suggest using a net name here" Mill-Max_0312-0-15-15-34-27-10-0 5681.32,3967.63 r0 top
J42 "Suggest using a net name here" Mill-Max_0312-0-15-15-34-27-10-0 6881.32,6848.52 r0 top
J43 "Suggest using a net name here" Mill-Max_0312-0-15-15-34-27-10-0 6681.32,6848.52 r0 top
J44 "Suggest using a net name here" Mill-Max_0312-0-15-15-34-27-10-0 6881.32,2046.37 r0 top
J45 "Suggest using a net name here" Mill-Max_0312-0-15-15-34-27-10-0 6881.32,7810.15 r0 top
J46 "Suggest using a net name here" Mill-Max_0312-0-15-15-34-27-10-0 6381.32,6847.73 r0 top
J47 "Suggest using a net name here" Mill-Max_0312-0-15-15-34-27-10-0 6881.32,4928.26 r0 top
J48 "Suggest using a net name here" Mill-Max_0312-0-15-15-34-27-10-0 6681.32,2046.37 r0 top
J49 "Suggest using a net name here" Mill-Max_0312-0-15-15-34-27-10-0 6681.32,7810.15 r0 top
J50 "Suggest using a net name here" Mill-Max_0312-0-15-15-34-27-10-0 6181.32,6847.73 r0 top
J51 "Suggest using a net name here" Mill-Max_0312-0-15-15-34-27-10-0 6681.32,4928.26 r0 top
J52 "Suggest using a net name here" Mill-Max_0312-0-15-15-34-27-10-0 6381.32,2046.37 r0 top
J53 "Suggest using a net name here" Mill-Max_0312-0-15-15-34-27-10-0 6381.32,7810.15 r0 top
J54 "Suggest using a net name here" Mill-Max_0312-0-15-15-34-27-10-0 6181.32,2046.37 r0 top
J55 "Suggest using a net name here" Mill-Max_0312-0-15-15-34-27-10-0 6181.32,7810.15 r0 top
J56 "Suggest using a net name here" Mill-Max_0312-0-15-15-34-27-10-0 5881.32,6849.52 r0 top
J57 "Suggest using a net name here" Mill-Max_0312-0-15-15-34-27-10-0 6381.32,4928.26 r0 top
J58 "Suggest using a net name here" Mill-Max_0312-0-15-15-34-27-10-0 5681.32,6849.52 r0 top
J59 "Suggest using a net name here" Mill-Max_0312-0-15-15-34-27-10-0 6181.32,4928.26 r0 top
J60 "Suggest using a net name here" Mill-Max_0312-0-15-15-34-27-10-0 5781.32,2046.37 r0 top
J61 "Suggest using a net name here" Mill-Max_0312-0-15-15-34-27-10-0 5781.32,7810.15 r0 top
J62 "Suggest using a net name here" Mill-Max_0312-0-15-15-34-27-10-0 5781.32,4928.26 r0 top
J63 "Suggest using a net name here" Mill-Max_0312-0-15-15-34-27-10-0 5581.32,2046.37 r0 top
J64 "Suggest using a net name here" Mill-Max_0312-0-15-15-34-27-10-0 5581.32,7810.15 r0 top
J65 "Suggest using a net name here" Mill-Max_0312-0-15-15-34-27-10-0 5581.32,4928.26 r0 top
J66 "74650073R" Wurth_WP-THRBU 11561.45,2861 r0 top locked
J67 "74650073R" Wurth_WP-THRBU 219.06,1820.38 r0 top
J68 "74650073R" Wurth_WP-THRBU 218.06,4387.57 r0 top
J69 "74650073R" Wurth_WP-THRBU 250.06,7188.22 r0 top
J70 "74650073R" Wurth_WP-THRBU 227.95,8417.55 r0 top
J71 "HSEC8-160-01-L-DV-A-BL" controlCARD-120HSEC 10447.81,8305.87 r180 top locked
J72 "61300211121" WURTH_61300211121 2740,8493.92 r180 top
J74 "691214110002" Wurth_691214110002 11654,6531.1 r270 top
J75 "61300311121" WURTH_61300311121 11700,5879 r90 top
J76 "310-13-102-41-001000" Mill-max_310-13-102-41-001000 11700,4080 r90 top
J77 "310-13-102-41-001000" Mill-max_310-13-102-41-001000 11700,3580 r90 top
J78 "310-13-104-41-001000" Mill-max_310-13-104-41-001000 11700,4880 r90 top
J79 "61300211121" WURTH_61300211121 8285,77 r0 top
J80 "61300211121" WURTH_61300211121 8285,2958 r0 top
J81 "61300211121" WURTH_61300211121 8285,5837 r0 top
K1 "G4A-1A-PE DC12" RELAY_G4A-1A-PE 628,339 r180 top locked
K2 "G4A-1A-PE DC12" RELAY_G4A-1A-PE 633.56,1245.38 r180 top locked
K3 "G4A-1A-PE DC12" RELAY_G4A-1A-PE 633.69,2901.94 r180 top locked
K4 "G4A-1A-PE DC12" RELAY_G4A-1A-PE 629.56,3813.38 r180 top locked
K5 "G4A-1A-PE DC12" RELAY_G4A-1A-PE 632,5716 r180 top locked
K6 "G4A-1A-PE DC12" RELAY_G4A-1A-PE 629.56,6628.38 r180 top locked
L1 "7443783533220" FP-7443783533220_PTH_34MM5_36MM-MFG 1977.39,702.51 r0 top locked
L2 "750344413" 750344413 4282.34,816 r180 top locked value=480uH
L3 "7443783533220" FP-7443783533220_PTH_34MM5_36MM-MFG 1977.39,3268.51 r0 top locked
L4 "750344413" 750344413 4282.34,3395 r180 top locked value=480uH
L5 "7443783533220" FP-7443783533220_PTH_34MM5_36MM-MFG 1975.39,6081.51 r0 top locked
L6 "750344413" 750344413 4282.34,6185 r180 top locked value=480uH
L7 "74279228260" 0603 2662.46,8255.85 r180 bottom value="26 ohm"
L8 "74279228260" 0603 2182.98,8325.97 r270 bottom value="26 ohm"
L9 "74279228260" 0603 9707,7799 r270 bottom value="26 ohm"
L10 "74279228260" 0603 4089,7923 r90 bottom value="26 ohm"
L11 "74279228260" 0603 3534.94,2331.78 r0 bottom value="26 ohm"
L12 "74279228260" 0603 3532.93,4913.74 r0 bottom value="26 ohm"
L13 "74279228260" 0603 3535,7716.78 r0 bottom value="26 ohm"
L14 "XAL4030-332MEB" XAL4030 11701,7201.91 r90 bottom value=3.3uH
LBL1 "THT-14-423-10" Label_650x200 9489,373.55 r0 top
Logo1 "WEEE logo" WEEE_Minimum 1055.11,8119 r0 top
Logo2 "Pb-Free Symbol" Pb-Free_Overlay_Medium 11341.92,7324 r0 top
Logo3 "FCC disclaimer" FCC_disclaimer 10705,-2146.45 r0 top
Logo4 "CAUTION.  READ USER GUIDE BEFORE USE" IEC_Caution_Medium 609.43,7899 r0 top
Logo5 "ESD Susceptible" ESD_Overlay_Medium 11337,7580 r0 top
LOGO6 "DANGER HIGH VOLTAGE" IEC_HighVoltage_Medium 10785.45,1306 r0 top
LOGO7 "DANGER HIGH VOLTAGE" IEC_HighVoltage_Medium 1239,7278 r0 top
LOGO8 "DANGER HIGH VOLTAGE" IEC_HighVoltage_Medium 1239,4498.5 r0 top
LOGO9 "DANGER HIGH VOLTAGE" IEC_HighVoltage_Medium 1239,1935 r0 top
LOGO10 "CAUTION HOT SURFACE" IEC_HotSurface_Medium 4771,7640.14 r0 top
LOGO11 "CAUTION HOT SURFACE" IEC_HotSurface_Medium 4771,4569 r0 top
LOGO12 "CAUTION HOT SURFACE" IEC_HotSurface_Medium 4771,1885 r0 top
LOGO13 "DANGER HIGH VOLTAGE" IEC_HighVoltage_Medium 10785.45,4859 r0 top
Logo15 "CE Mark" CE_Mark_5mm 1379.11,8045.51 r0 top
LOGO16 "CAUTION HOT SURFACE" IEC_HotSurface_Medium 9414,5826 r0 top
LOGO17 "CAUTION HOT SURFACE" IEC_HotSurface_Medium 9414,2258 r0 top
Q1 "BSS138PW,115" SOT-323 393,114 r270 bottom value=60V
Q2 "BSS138PW,115" SOT-323 393,2679 r270 bottom value=60V
Q3 "BSS138PW,115" SOT-323 393,5493 r270 bottom value=60V
Q4 "BSS138PW,115" SOT-323 393,1024 r270 bottom value=60V
Q5 "BSS138PW,115" SOT-323 393,3588 r270 bottom value=60V
Q6 "BSS138PW,115" SOT-323 393,6403 r270 bottom value=60V
Q7 "BSS138PW,115" SOT-323 8382,160 r270 bottom value=60V
Q8 "BSS138PW,115" SOT-323 8380,3041.5 r270 bottom value=60V
Q9 "BSS138PW,115" SOT-323 8380,5921 r270 bottom value=60V
R1 "RC1206FR-07100KL" 1206 11566,603.23 r270 bottom value=100k
R2 "RC1206FR-07100KL" 1206 11566,803.8 r270 bottom value=100k
R3 "WSL40262L000FEB" WSL4026_310 3275,1435 r180 bottom value=0.002
R4 "RC1206FR-07100KL" 1206 11566,1004.37 r270 bottom value=100k
R5 "RC1206FR-07100KL" 1206 11566,1204.94 r270 bottom value=100k
R6 "WSL40262L000FEB" WSL4026_310 3276.93,4015 r180 bottom value=0.002
R7 "RC1206FR-07100KL" 1206 11570,1899.52 r270 bottom value=100k
R8 "RC1206FR-07100KL" 1206 11570,2100.09 r270 bottom value=100k
R9 "WSL40262L000FEB" WSL4026_310 3278,6816 r180 bottom value=0.002
R10 "RC1206FR-07100KL" 1206 11570,2300.66 r270 bottom value=100k
R11 "RC1206FR-07100KL" 1206 11570,2501.23 r270 bottom value=100k
R12 "35222R2JT" 2512 3327,139 r180 bottom value=2.2
R13 "35222R2JT" 2512 3327,278 r180 bottom value=2.2
R14 "35222R2JT" 2512 3327,417 r180 bottom value=2.2
R15 "35222R2JT" 2512 3338,2773 r180 bottom value=2.2
R16 "35222R2JT" 2512 3338,2912 r180 bottom value=2.2
R17 "35222R2JT" 2512 3338.02,3051 r180 bottom value=2.2
R18 "35222R2JT" 2512 3331.66,5505 r180 bottom value=2.2
R19 "35222R2JT" 2512 3332,5644 r180 bottom value=2.2
R20 "35222R2JT" 2512 3332,5783 r180 bottom value=2.2
R21 "ESR03EZPJ101" 0603 478,198 r180 bottom value=100
R22 "ESR03EZPJ101" 0603 485,2763 r180 bottom value=100
R23 "ESR03EZPJ101" 0603 483,5577 r180 bottom value=100
R24 "ESR03EZPJ101" 0603 479,1110 r180 bottom value=100
R25 "ESR03EZPJ101" 0603 484,3673 r180 bottom value=100
R26 "ESR03EZPJ101" 0603 483,6489 r180 bottom value=100
R27 "ERJ-3EKF1002V" 0603 347,198 r0 bottom value=10.0k
R28 "ERJ-3EKF1002V" 0603 347,2763 r0 bottom value=10.0k
R29 "ERJ-3EKF1002V" 0603 347,5577 r0 bottom value=10.0k
R30 "ERJ-3EKF1002V" 0603 347,1110 r0 bottom value=10.0k
R31 "ERJ-3EKF1002V" 0603 347,3673 r0 bottom value=10.0k
R32 "ERJ-3EKF1002V" 0603 347,6489 r0 bottom value=10.0k
R33 "RG1608P-123-B-T5" 0603 2387.29,7899.53 r270 bottom value=12.0k
R34 "RG1608P-123-B-T5" 0603 2048.98,8087.4 r0 bottom value=12.0k
R35 "RT0603BRD0710K5L" 0603 9573.59,7627.47 r0 bottom value=10.5k
R36 "TNPV12061M00BEEN" TNPV1206 1484.47,7410 r0 bottom value=1.00Meg
R37 "TNPV12061M00BEEN" TNPV1206 1786,7567 r0 bottom value=1.00Meg
R38 "TNPV12061M00BEEN" TNPV1206 2062,7655 r0 bottom value=1.00Meg
R39 "TNPV12061M00BEEN" TNPV1206 1484,7519 r0 bottom value=1.00Meg
R40 "TNPV12061M00BEEN" TNPV1206 1786,7675 r0 bottom value=1.00Meg
R41 "TNPV12061M00BEEN" TNPV1206 1978,7856 r90 bottom value=1.00Meg
R42 "TNPV12061M00BEEN" TNPV1206 9710,7055 r90 bottom value=1.00Meg
R43 "TNPV12061M00BEEN" TNPV1206 9643,7259 r90 bottom value=1.00Meg
R44 "TNPV12061M00BEEN" TNPV1206 9537,7420 r90 bottom value=1.00Meg
R45 "CRCW060368R1FKEA" 0603 2263,7900 r90 bottom value=68.1
R46 "CRCW060368R1FKEA" 0603 2249,8326.5 r90 bottom value=68.1
R47 "CRCW060368R1FKEA" 0603 9675,7692 r0 bottom value=68.1
R48 "TNPV12061M00BEEN" TNPV1206 1831,7222 r90 bottom value=1.00Meg
R49 "TNPV12061M00BEEN" TNPV1206 2053,7425 r90 bottom value=1.00Meg
R50 "TNPV12061M00BEEN" TNPV1206 2226,7594 r90 bottom value=1.00Meg
R51 "TNPV12061M00BEEN" TNPV1206 993,7556.15 r0 bottom value=1.00Meg
R52 "TNPV12061M00BEEN" TNPV1206 1496,7824 r0 bottom value=1.00Meg
R53 "TNPV12061M00BEEN" TNPV1206 1805,7907 r0 bottom value=1.00Meg
R54 "TNPV12061M00BEEN" TNPV1206 10002.86,7105 r90 bottom value=1.00Meg
R55 "TNPV12061M00BEEN" TNPV1206 9860,7266.01 r90 bottom value=1.00Meg
R56 "TNPV12061M00BEEN" TNPV1206 9695,7449.53 r180 bottom value=1.00Meg
R57 "RG1608P-123-B-T5" 0603 2355.83,8008.53 r0 bottom value=12.0k
R58 "RG1608P-123-B-T5" 0603 1931.53,8119.94 r90 bottom value=12.0k
R59 "RT0603BRD0710K5L" 0603 9467,7595.63 r90 bottom value=10.5k
R60 "RG1608P-123-B-T5" 0603 2758.92,7898.53 r270 bottom value=12.0k
R61 "RG1608P-123-B-T5" 0603 1752.98,8087.4 r180 bottom value=12.0k
R62 "RT0603BRD0710K5L" 0603 9294.17,7564.63 r180 bottom value=10.5k
R63 "TNPV12061M00BEEN" TNPV1206 2525.07,7143.23 r90 bottom value=1.00Meg
R64 "TNPV12061M00BEEN" TNPV1206 2577,7413 r90 bottom value=1.00Meg
R65 "TNPV12061M00BEEN" TNPV1206 2575.76,7614 r90 bottom value=1.00Meg
R66 "TNPV12061M00BEEN" TNPV1206 964,8158.73 r0 bottom value=1.00Meg
R67 "TNPV12061M00BEEN" TNPV1206 1245,8245 r0 bottom value=1.00Meg
R68 "TNPV12061M00BEEN" TNPV1206 1550,8271 r0 bottom value=1.00Meg
R69 "TNPV12061M00BEEN" TNPV1206 9360,6955 r90 bottom value=1.00Meg
R70 "TNPV12061M00BEEN" TNPV1206 9299,7186 r90 bottom value=1.00Meg
R71 "TNPV12061M00BEEN" TNPV1206 9284,7420 r90 bottom value=1.00Meg
R72 "CRCW060368R1FKEA" 0603 2691,7807 r270 bottom value=68.1
R73 "CRCW060368R1FKEA" 0603 1690,8247.64 r90 bottom value=68.1
R74 "CRCW060368R1FKEA" 0603 9188.79,7693.99 r180 bottom value=68.1
R75 "TNPV12061M00BEEN" TNPV1206 2114,7027.99 r90 bottom value=1.00Meg
R76 "TNPV12061M00BEEN" TNPV1206 2275,7294 r90 bottom value=1.00Meg
R77 "TNPV12061M00BEEN" TNPV1206 2409,7625 r90 bottom value=1.00Meg
R78 "TNPV12061M00BEEN" TNPV1206 775.6,7869 r0 bottom value=1.00Meg
R79 "TNPV12061M00BEEN" TNPV1206 1324,8037 r0 bottom value=1.00Meg
R80 "TNPV12061M00BEEN" TNPV1206 1550,8121 r0 bottom value=1.00Meg
R81 "TNPV12061M00BEEN" TNPV1206 9604.37,7055 r90 bottom value=1.00Meg
R82 "TNPV12061M00BEEN" TNPV1206 9489.76,7220.01 r90 bottom value=1.00Meg
R83 "TNPV12061M00BEEN" TNPV1206 9412.62,7420 r90 bottom value=1.00Meg
R84 "RG1608P-123-B-T5" 0603 2791.83,8008.46 r180 bottom value=12.0k
R85 "RG1608P-123-B-T5" 0603 1865,8119.94 r90 bottom value=12.0k
R86 "RT0603BRD0710K5L" 0603 9405.17,7595.63 r90 bottom value=10.5k
R87 "RG1608P-123-B-T5" 0603 1752.98,8562.54 r180 bottom value=12.0k
R88 "RG1608P-123-B-T5" 0603 2758.38,8187.17 r90 bottom value=12.0k
R89 "TNPV12061M00BEEN" TNPV1206 2630.07,7144.23 r90 bottom value=1.00Meg
R90 "TNPV12061M00BEEN" TNPV1206 2682,7414 r90 bottom value=1.00Meg
R91 "TNPV12061M00BEEN" TNPV1206 2682,7614.24 r90 bottom value=1.00Meg
R92 "TNPV12061M00BEEN" TNPV1206 963.24,8262.84 r0 bottom value=1.00Meg
R93 "TNPV12061M00BEEN" TNPV1206 1246,8351 r0 bottom value=1.00Meg
R94 "TNPV12061M00BEEN" TNPV1206 1550,8375 r0 bottom value=1.00Meg
R95 "CRCW060368R1FKEA" 0603 2919.2,8219.02 r0 bottom value=68.1
R96 "CRCW060368R1FKEA" 0603 1690,8403 r270 bottom value=68.1
R97 "TNPV12061M00BEEN" TNPV1206 3006,7195 r180 bottom value=1.00Meg
R98 "TNPV12061M00BEEN" TNPV1206 2929.24,7359.94 r90 bottom value=1.00Meg
R99 "TNPV12061M00BEEN" TNPV1206 2882,7607 r90 bottom value=1.00Meg
R100 "TNPV12061M00BEEN" TNPV1206 711.54,8559.39 r0 bottom value=1.00Meg
R101 "TNPV12061M00BEEN" TNPV1206 1024,8558 r0 bottom value=1.00Meg
R102 "TNPV12061M00BEEN" TNPV1206 1550,8532 r0 bottom value=1.00Meg
R103 "RG1608P-123-B-T5" 0603 2791.72,8078.05 r180 bottom value=12.0k
R104 "RG1608P-123-B-T5" 0603 1865,8530 r270 bottom value=12.0k
R105 "RCS06030000Z0EA" 0603 10153.72,8456 r180 bottom value=0
R106 "RCS06030000Z0EA" 0603 9771,8455.57 r180 bottom value=0
R107 "RG1608P-103-B-T5" 0603 9213,7805 r90 bottom value=10.0k
R108 "CRCW060368R1FKEA" 0603 9807,8053 r0 bottom value=68.1
R109 "RCS06030000Z0EA" 0603 9561,8455.57 r0 bottom value=0
R110 "RCS06030000Z0EA" 0603 9412.5,8328 r0 bottom value=0
R111 "RG1608P-103-B-T5" 0603 9442.14,7975.27 r180 bottom value=10.0k
R112 "PHT0603Y1002BGT200" 0603 4145.47,8050.91 r270 bottom value=10.0k
R113 "RC0603FR-0749R9L" 0603 3251.89,2301.78 r90 bottom value=49.9
R114 "RT0603BRD0715KL" 0603 4222.47,8110.91 r270 bottom value=15.0k
R115 "CRCW060310R0FKEA" 0603 3244,1648 r90 bottom value=10.0
R116 "CRCW0603499RFKEAC" 0603 10217,8519.47 r0 bottom value=499
R117 "RC0603FR-0749R9L" 0603 3313.87,2301.78 r90 bottom value=49.9
R118 "RT0603BRD0715KL" 0603 4285.47,8110.91 r270 bottom value=15.0k
R119 "CRCW060310R0FKEA" 0603 3309.91,1648 r90 bottom value=10.0
R120 "PHT0603Y1002BGT200" 0603 4348.47,8110.91 r270 bottom value=10.0k
R121 "PHT0603Y1002BGT200" 0603 4467.47,8027.63 r180 bottom value=10.0k
R122 "RC0603FR-0749R9L" 0603 3247.86,4883 r90 bottom value=49.9
R123 "RT0603BRD0715KL" 0603 4467.47,7952.76 r180 bottom value=15.0k
R124 "CRCW060310R0FKEA" 0603 3244.44,4228 r90 bottom value=10.0
R125 "CRCW0603499RFKEAC" 0603 9899,8488.49 r0 bottom value=499
R126 "RC0603FR-0749R9L" 0603 3311.86,4882.74 r90 bottom value=49.9
R127 "RT0603BRD0715KL" 0603 4467.47,7889.91 r180 bottom value=15.0k
R128 "CRCW060310R0FKEA" 0603 3309.93,4228 r90 bottom value=10.0
R129 "PHT0603Y1002BGT200" 0603 4467.47,7826.91 r180 bottom value=10.0k
R130 "PHT0603Y1002BGT200" 0603 4436.47,7706.91 r90 bottom value=10.0k
R131 "RC0603FR-0749R9L" 0603 3247.93,7687 r90 bottom value=49.9
R132 "RT0603BRD0715KL" 0603 4362.53,7658.91 r90 bottom value=15.0k
R133 "CRCW060310R0FKEA" 0603 3244.54,7031 r90 bottom value=10.0
R134 "CRCW0603499RFKEAC" 0603 10441,8425 r0 bottom value=499
R135 "RC0603FR-0749R9L" 0603 3311,7687 r90 bottom value=49.9
R136 "RT0603BRD0715KL" 0603 4299.53,7658.91 r90 bottom value=15.0k
R137 "CRCW060310R0FKEA" 0603 3310.54,7031 r90 bottom value=10.0
R138 "RG1608P-103-B-T5" 0603 2533.02,8255.85 r180 bottom value=10.0k
R139 "PHT0603Y1002BGT200" 0603 4226,7659.14 r270 bottom value=10.0k
R140 "CRCW060368R1FKEA" 0603 4848,8237 r0 bottom value=68.1
R141 "RG1608P-103-B-T5" 0603 2533,8385 r0 bottom value=10.0k
R142 "RC0603FR-072K26L" 0603 5025.55,7597.06 r180 bottom value=2.26k
R143 "RC0603FR-07820RL" 0603 11633,7804.19 r180 bottom value=820
R144 "RC0603FR-0756K2L" 0603 11414.52,7149.6 r90 bottom value=56.2k
R145 "ERJ-3EKF1002V" 0603 11478,7024 r90 bottom value=10.0k
R146 "RC0603FR-072K26L" 0603 5025,4561 r180 bottom value=2.26k
R147 "RC0603FR-071K69L" 0603 7802,1471 r90 bottom value=1.69k
R148 "RC0603FR-072K26L" 0603 5027,1849 r180 bottom value=2.26k
R149 "ESR03EZPJ101" 0603 8265.5,155.73 r0 bottom value=100
R150 "RC0603FR-073K3L" 0603 7704,1503.26 r0 bottom value=3.30k
R151 "ERJ-3EKF1002V" 0603 8466,149 r270 bottom value=10.0k
R152 "RC0603FR-071K69L" 0603 7793,4349 r90 bottom value=1.69k
R153 "ESR03EZPJ101" 0603 8263.5,3038 r0 bottom value=100
R154 "RC0603FR-073K3L" 0603 7695,4316 r0 bottom value=3.30k
R155 "ERJ-3EKF1002V" 0603 8464,3040 r270 bottom value=10.0k
R156 "RC0603FR-072K26L" 0603 11465.73,8101.75 r180 bottom value=2.26k
R157 "RC0603FR-071K69L" 0603 7793,7233.91 r90 bottom value=1.69k
R158 "ESR03EZPJ101" 0603 8263,5918 r0 bottom value=100
R159 "RC0603FR-073K3L" 0603 7695.21,7201 r0 bottom value=3.30k
R160 "ERJ-3EKF1002V" 0603 8462,5964 r270 bottom value=10.0k
R161 "RC0603FR-07820RL" 0603 10103,8070.53 r0 top value=820
R162 "35222R2JT" 2512 3327,556 r180 bottom value=2.2
R163 "35222R2JT" 2512 3338,3194 r180 bottom value=2.2
R164 "35222R2JT" 2512 3332,5922 r180 bottom value=2.2
RT1 "B59751B0120A070" TDK_B751 1503,1535 r90 top locked value="50 ohm"
RT2 "B59751B0120A070" TDK_B751 1500,4097 r90 top locked value="50 ohm"
RT3 "B59751B0120A070" TDK_B751 1495,6910 r90 top locked value="50 ohm"
TP1 "5000" Keystone5000 11718,576 r90 top
TP2 "5003" Keystone5003 2390.77,1472.23 r90 top
TP3 "5002" Keystone5002 5084,1113 r90 top
TP4 "5003" Keystone5003 2389,4023 r90 top
TP5 "5001" Keystone5001 11718,1266 r90 top
TP6 "5002" Keystone5002 5101,3976 r90 top
TP7 "5003" Keystone5003 2389,5309 r90 top
TP8 "5002" Keystone5002 5053,5907 r90 top
TP9 "5004" Keystone5004 11732,2556 r90 top
TP10 "5003" Keystone5003 110.5,2142.38 r90 top
TP11 "5003" Keystone5003 112.56,4709.38 r90 top
TP12 "5003" Keystone5003 141.56,7516.38 r90 top
TP13 "5001" Keystone5001 142,8128 r90 top
TP14 "5000" Keystone5000 9879,7561.36 r90 top
TP15 "5001" Keystone5001 5032,8128 r90 top
TP16 "5015" Testpoint_Keystone_Miniature 2166,7869 r270 bottom
TP17 "5015" Testpoint_Keystone_Miniature 9732,7564.65 r180 bottom
TP18 "5015" Testpoint_Keystone_Miniature 2194,8204 r180 bottom
TP19 "5015" Testpoint_Keystone_Miniature 2919,7887 r270 bottom
TP20 "5015" Testpoint_Keystone_Miniature 1643,8216.12 r180 top
TP21 "5015" Testpoint_Keystone_Miniature 9156,7577.33 r270 bottom
TP22 "5015" Testpoint_Keystone_Miniature 2888,8316 r180 bottom
TP23 "5015" Testpoint_Keystone_Miniature 1643,8433.19 r180 top
TP24 "5015" Testpoint_Keystone_Miniature 1982,8558.3 r180 bottom
TP25 "5015" Testpoint_Keystone_Miniature 9688.64,7948.98 r270 bottom
TP26 "5015" Testpoint_Keystone_Miniature 4029,8074 r180 bottom
TP27 "5015" Testpoint_Keystone_Miniature 4562,8175 r180 bottom
TP28 "5015" Testpoint_Keystone_Miniature 4551,7679 r180 bottom
TP29 "5015" Testpoint_Keystone_Miniature 10990.19,7268 r90 bottom
TP30 "5015" Testpoint_Keystone_Miniature 10653,7300 r180 bottom
TP31 "5015" Testpoint_Keystone_Miniature 10472,8153.63 r0 bottom
TP32 "5015" Testpoint_Keystone_Miniature 11052.41,7630.06 r180 bottom
TP33 "5015" Testpoint_Keystone_Miniature 10638,7633.36 r0 bottom
TP34 "5015" Testpoint_Keystone_Miniature 10227,7632.66 r180 bottom
TP35 "5000" Keystone5000 11666,8039 r90 top
TP36 "5000" Keystone5000 11665,7892.13 r90 top
TP37 "5001" Keystone5001 11338.05,7869.15 r90 top
TP38 "5000" Keystone5000 9957,7844.85 r90 top
U1 "TLV9004IDR" D0014A_N 2573.83,8043.53 r0 bottom
U2 "TLV9004IDR" D0014A_N 1900.98,8324.97 r90 bottom
U3 "TLV9004IDR" D0014A_N 9431.14,7801.27 r90 bottom
U4 "AMC3301DWER" DWE0016A 3379.94,2002.93 r90 bottom
U5 "OPA4376AIPW" PW0014A_N 4292.5,7884.91 r270 bottom
U6 "AMC3301DWER" DWE0016A 3379.93,4583.93 r90 bottom
U7 "AMC3301DWER" DWE0016A 3380,7387.93 r90 bottom
U8 "SN74LVC08APWR" PW0014A_N 11019.35,7795.18 r180 bottom
U9 "SN74LVC32APWRG3" PW0014A_N 11019.35,7467.1 r180 bottom
U10 "SN74LVC08APWR" PW0014A_N 10620.32,7795.18 r180 bottom
U11 "SN74LVC32APWRG3" PW0014A_N 10620.32,7467.1 r180 bottom
U12 "SN74LVC08APWR" PW0014A_N 10235.19,7794.78 r180 bottom
U13 "SN74LVC32APWRG3" PW0014A_N 10235.19,7466.71 r180 bottom
U14 "LMT87LPM" LP0003A 5122,7597 r180 top
U15 "TPS563200DDCR" DDC0006A_N 11527,7155.91 r180 bottom
U16 "LP5907MFX-3.3/NOPB" DBV0005A_N 11628,7626.91 r90 bottom
U17 "LMT87LPM" LP0003A 5121.95,4560 r180 top
U18 "LMT87LPM" LP0003A 5121.95,1848 r180 top
U19 "SN74LVC1G08DCKT" DCK0005A_N 7694.09,1356.31 r0 bottom
U20 "SN74LVC1G08DCKT" DCK0005A_N 7694.09,4238.2 r0 bottom
U21 "LMT87QDCKRQ1" DCK0005A_N 11461.44,8180.34 r180 bottom
U22 "SN74LVC1G08DCKT" DCK0005A_N 7694.09,7120.09 r0 bottom
ZZ1 "This Assembly Note is for PCB labels only" AssemblyNoteLabel 219.45,9207 r0 top
ZZ2 "These assemblies are ESD sensitive, ESD precautions shall be observed." AssemblyNote 219.45,9098.11 r0 top
ZZ3 "These assemblies must be clean and free from flux and all contaminants. Use of no clean flux is not acceptable." AssemblyNote 219.45,9009.56 r0 top
ZZ4 "These assemblies must comply with workmanship standards IPC-A-610 Class 2, unless otherwise specified." AssemblyNote 219.45,8921 r0 top

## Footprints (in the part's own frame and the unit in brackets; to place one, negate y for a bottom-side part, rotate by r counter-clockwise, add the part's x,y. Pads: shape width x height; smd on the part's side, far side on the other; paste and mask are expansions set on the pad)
0603 [mm] "0603 from SM-752 data"
  rect 1x0.95 smd: 1(-0.8,0) 2(0.8,0)
  silkscreen extent -1.52,-0.69 1.52,0.69, body extent -0.87,-0.47 0.87,0.47, height 1
1206 [mm] "1206 from SM-752 data"
  rect 1.3x1.85 smd: 1(-1.45,0) 2(1.45,0)
  silkscreen extent -2.4,-1.21 2.4,1.21, body extent -1.7,-0.9 1.7,0.9, height 1.35
1206_180 [mm] "1206_180"
  rect 1.1x1.6 smd: 1(-1.7,0) 2(1.7,0)
  silkscreen extent -0.9,-1 0.9,1, body extent -1.75,-0.95 1.75,0.95, height 1.8
1206_190 [mm] "1206_190"
  rect 1.1x1.6 smd: 1(-1.7,0) 2(1.7,0)
  silkscreen extent -0.9,-1 0.9,1, body extent -1.75,-0.95 1.75,0.95, height 1.9
2512 [mm] "Chip Resistor, Body 6.3x3.2mm, IPC Medium Density"
  rect 1.3x3.4 smd: 1(-2.95,0) 2(2.95,0)
  silkscreen extent -1.9,-1.6 1.9,1.6, body extent -3.22,-1.67 3.22,1.67, height 0.71
750344413 [mm] "Inductor, TH, 2-Leads, Body 36x40mm"
  oval 2.2x12 hole 1.5 slot 8 at 90 deg: 1(-18,0) 2(-14,0)
  silkscreen extent -18,-20 18,20
AssemblyNote [mil] "Assembly Note"
AssemblyNoteLabel [mil] "Assembly Note for PCB Labels"
B32924_31mm [mm] "Epcos film capacitors, 27.5mm spacing"
  rect 1.5x1.5 hole 1: 1(-13.75,0)
  round 1.5 hole 1: 2(13.75,0)
  silkscreen extent -15.75,-10.5 15.75,10.5, body extent -15.75,-10.5 15.75,10.5, height 31
CAPPR250W50D630H1120 [mm] "PANASONIC"
  rect 1.25x1.25 hole 0.75: 1(-1.25,0)
  round 1.25 hole 0.75: 2(1.25,0)
  silkscreen extent -3.4,-3.4 3.4,3.4, body extent -3.37,-3.39 3.4,3.39, height 12.21
CE_Mark_5mm [mil] "Minimum text height for CE Mark"
  silkscreen extent -138,-98 138,98
controlCARD-120HSEC [mm] "Pads are not numbered according to Samtec datasheet."
  rect 0.5x2.724 smd: 1(-23.357,-1.678) 2(-23.357,1.722) 3(-22.557,-1.678) 4(-22.557,1.722) 5(-21.757,-1.678) 6(-21.757,1.722) 7(-20.957,-1.678) 8(-20.957,1.722) 9(-20.157,-1.678) 10(-20.157,1.722) 11(-19.357,-1.678) 12(-19.357,1.722) 13(-18.557,-1.678) 14(-18.557,1.722) 15(-17.757,-1.678) 16(-17.757,1.722) 17(-16.957,-1.678) 18(-16.957,1.722) 19(-16.157,-1.678) 20(-16.157,1.722) 21(-15.357,-1.678) 22(-15.357,1.722) 23(-14.557,-1.678) 24(-14.557,1.722) 25(-13.757,-1.678) 26(-13.757,1.722) 27(-12.957,-1.678) 28(-12.957,1.722) 29(-12.157,-1.678) 30(-12.157,1.722) 31(-11.357,-1.678) 32(-11.357,1.722) 33(-10.557,-1.678) 34(-10.557,1.722) 35(-9.757,-1.678) 36(-9.757,1.722) 37(-8.957,-1.678) 38(-8.957,1.722) 39(-8.157,-1.678) 40(-8.157,1.722) 41(-7.357,-1.678) 42(-7.357,1.722) 43(-6.557,-1.678) 44(-6.557,1.722) 45(-5.757,-1.678) 46(-5.757,1.722) 47(-4.957,-1.678) 48(-4.957,1.722) 49(-4.157,-1.678) 50(-4.157,1.722) 51(-3.357,-1.678) 52(-3.357,1.722) 53(-2.557,-1.678) 54(-2.557,1.722) 55(-1.757,-1.678) 56(-1.757,1.722) 57(2.243,-1.678) 58(2.243,1.722) 59(3.043,-1.678) 60(3.043,1.722) 61(3.843,-1.678) 62(3.843,1.722) 63(4.643,-1.678) 64(4.643,1.722) 65(5.443,-1.678) 66(5.443,1.722) 67(6.243,-1.678) 68(6.243,1.722) 69(7.043,-1.678) 70(7.043,1.722) 71(7.843,-1.678) 72(7.843,1.722) 73(8.643,-1.678) 74(8.643,1.722) 75(9.443,-1.678) 76(9.443,1.722) 77(10.243,-1.678) 78(10.243,1.722) 79(11.043,-1.678) 80(11.043,1.722) 81(11.843,-1.678) 82(11.843,1.722) 83(12.643,-1.678) 84(12.643,1.722) 85(13.443,-1.678) 86(13.443,1.722) 87(14.243,-1.678) 88(14.243,1.722) 89(15.043,-1.678) 90(15.043,1.722) 91(15.843,-1.678) 92(15.843,1.722) 93(16.643,-1.678) 94(16.643,1.722) 95(17.443,-1.678) 96(17.443,1.722) 97(18.243,-1.678) 98(18.243,1.722) 99(19.043,-1.678) 100(19.043,1.722) 101(19.843,-1.678) 102(19.843,1.722) 103(20.643,-1.678) 104(20.643,1.722) 105(21.443,-1.678) 106(21.443,1.722) 107(22.243,-1.678) 108(22.243,1.722) 109(23.043,-1.678) 110(23.043,1.722) 111(23.843,-1.678) 112(23.843,1.722) 113(24.643,-1.678) 114(24.643,1.722) 115(25.443,-1.678) 116(25.443,1.722) 117(26.243,-1.678) 118(26.243,1.722) 119(27.043,-1.678) 120(27.043,1.722)
  round 0.025 hole 1.27 unplated mask+0.876: 181(-24.857,0.022) 182(28.543,1.522)
  round 1.348 hole 0.84: 185(-27.207,0.022) 186(30.893,0.022)
  silkscreen extent -32.11,-3.86 35.8,3.9, body extent -31.75,-3.48 35.3,3.52, height 12.35
D0014A_N [mm] "SOIC, 14-Leads, Body 8.7x3.9mm, Pitch 1.27mm, IPC Medium Density"
  oval 1.45x0.6 smd: 1(-2.725,3.81) 2(-2.725,2.54) 3(-2.725,1.27) 4(-2.725,0) 5(-2.725,-1.27) 6(-2.725,-2.54) 7(-2.725,-3.81) 8(2.725,-3.81) 9(2.725,-2.54) 10(2.725,-1.27) 11(2.725,0) 12(2.725,1.27) 13(2.725,2.54) 14(2.725,3.81)
  silkscreen extent -3.3,-4.4 0.9,4.4, body extent -3.02,-4.32 3.02,4.32, height 1.6
DBV0005A_N [mm] "SOT23, 5-Leads, Body 2.9x1.6mm, Pitch 0.95mm, Lead Span 2.8mm, IPC Medium Density"
  rrect17% 1x0.6 smd: 1(-1.375,0.95) 2(-1.375,0) 3(-1.375,-0.95) 4(1.375,-0.95) 5(1.375,0.95)
  silkscreen extent -0.25,-1.55 0.25,1.55, body extent -1.42,-1.46 1.42,1.46, height 1.09
DCK0005A_N [mm] "SOT353, 5-Leads, Body 2x1.3mm, Pitch 0.65mm, Lead Span 2.1mm, IPC Medium Density"
  rrect25% 0.85x0.4 smd: 1(-1.125,0.65) 2(-1.125,0) 3(-1.125,-0.65) 4(1.125,-0.65) 5(1.125,0.65)
  silkscreen extent -0.15,-1.1 0.15,1.1, body extent -1.14,-1 1.14,1, height 0.95
DDC0006A_N [mm]
  rrect17% 1x0.6 smd: 1(-1.375,0.95) 2(-1.375,0) 3(-1.375,-0.95) 4(1.375,-0.95) 5(1.375,0) 6(1.375,0.95)
  silkscreen extent -1.75,-1.52 0.7,1.53, body extent -1.43,-1.48 1.43,1.49, height 0.92
DWE0016A [mm] "SOIC, 16-Leads, Body 10.5x7.6mm, Pitch 1.27mm"
  rrect17% 1.65x0.6 smd: 1(-4.875,4.445) 2(-4.875,3.175) 3(-4.875,1.905) 4(-4.875,0.635) 5(-4.875,-0.635) 6(-4.875,-1.905) 7(-4.875,-3.175) 8(-4.875,-4.445) 9(4.875,-4.445) 10(4.875,-3.175) 11(4.875,-1.905) 12(4.875,-0.635) 13(4.875,0.635) 14(4.875,1.905) 15(4.875,3.175) 16(4.875,4.445)
  silkscreen extent -3.8,-5.25 3.8,5.6, body extent -5.17,-5.15 5.17,5.15, height 2.59
ESD_Overlay_Medium [mil]
  silkscreen extent -127,-109 125,110
ESG157M500AQ5 [mm] "TH, 2-Leads, Dia 22mm, Pin Spacing 10mm"
  rect 2.5x2.5 hole 2: 1(-5,0)
  round 2.5 hole 2: 2(5,0)
  silkscreen extent -11.5,-11.5 11.5,11.5, body extent -11.5,-11.49 11.51,11.49, height 47.01
FCC_disclaimer [mil]
Fiducial10-30 [mm]
  round 1 smd mask+1: 1(0,0)
  Top Layer keep-out circle w1.678: c0,0 r0.75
